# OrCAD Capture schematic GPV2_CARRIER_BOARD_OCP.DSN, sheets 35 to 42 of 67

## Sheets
35 040 M.2_L: size C
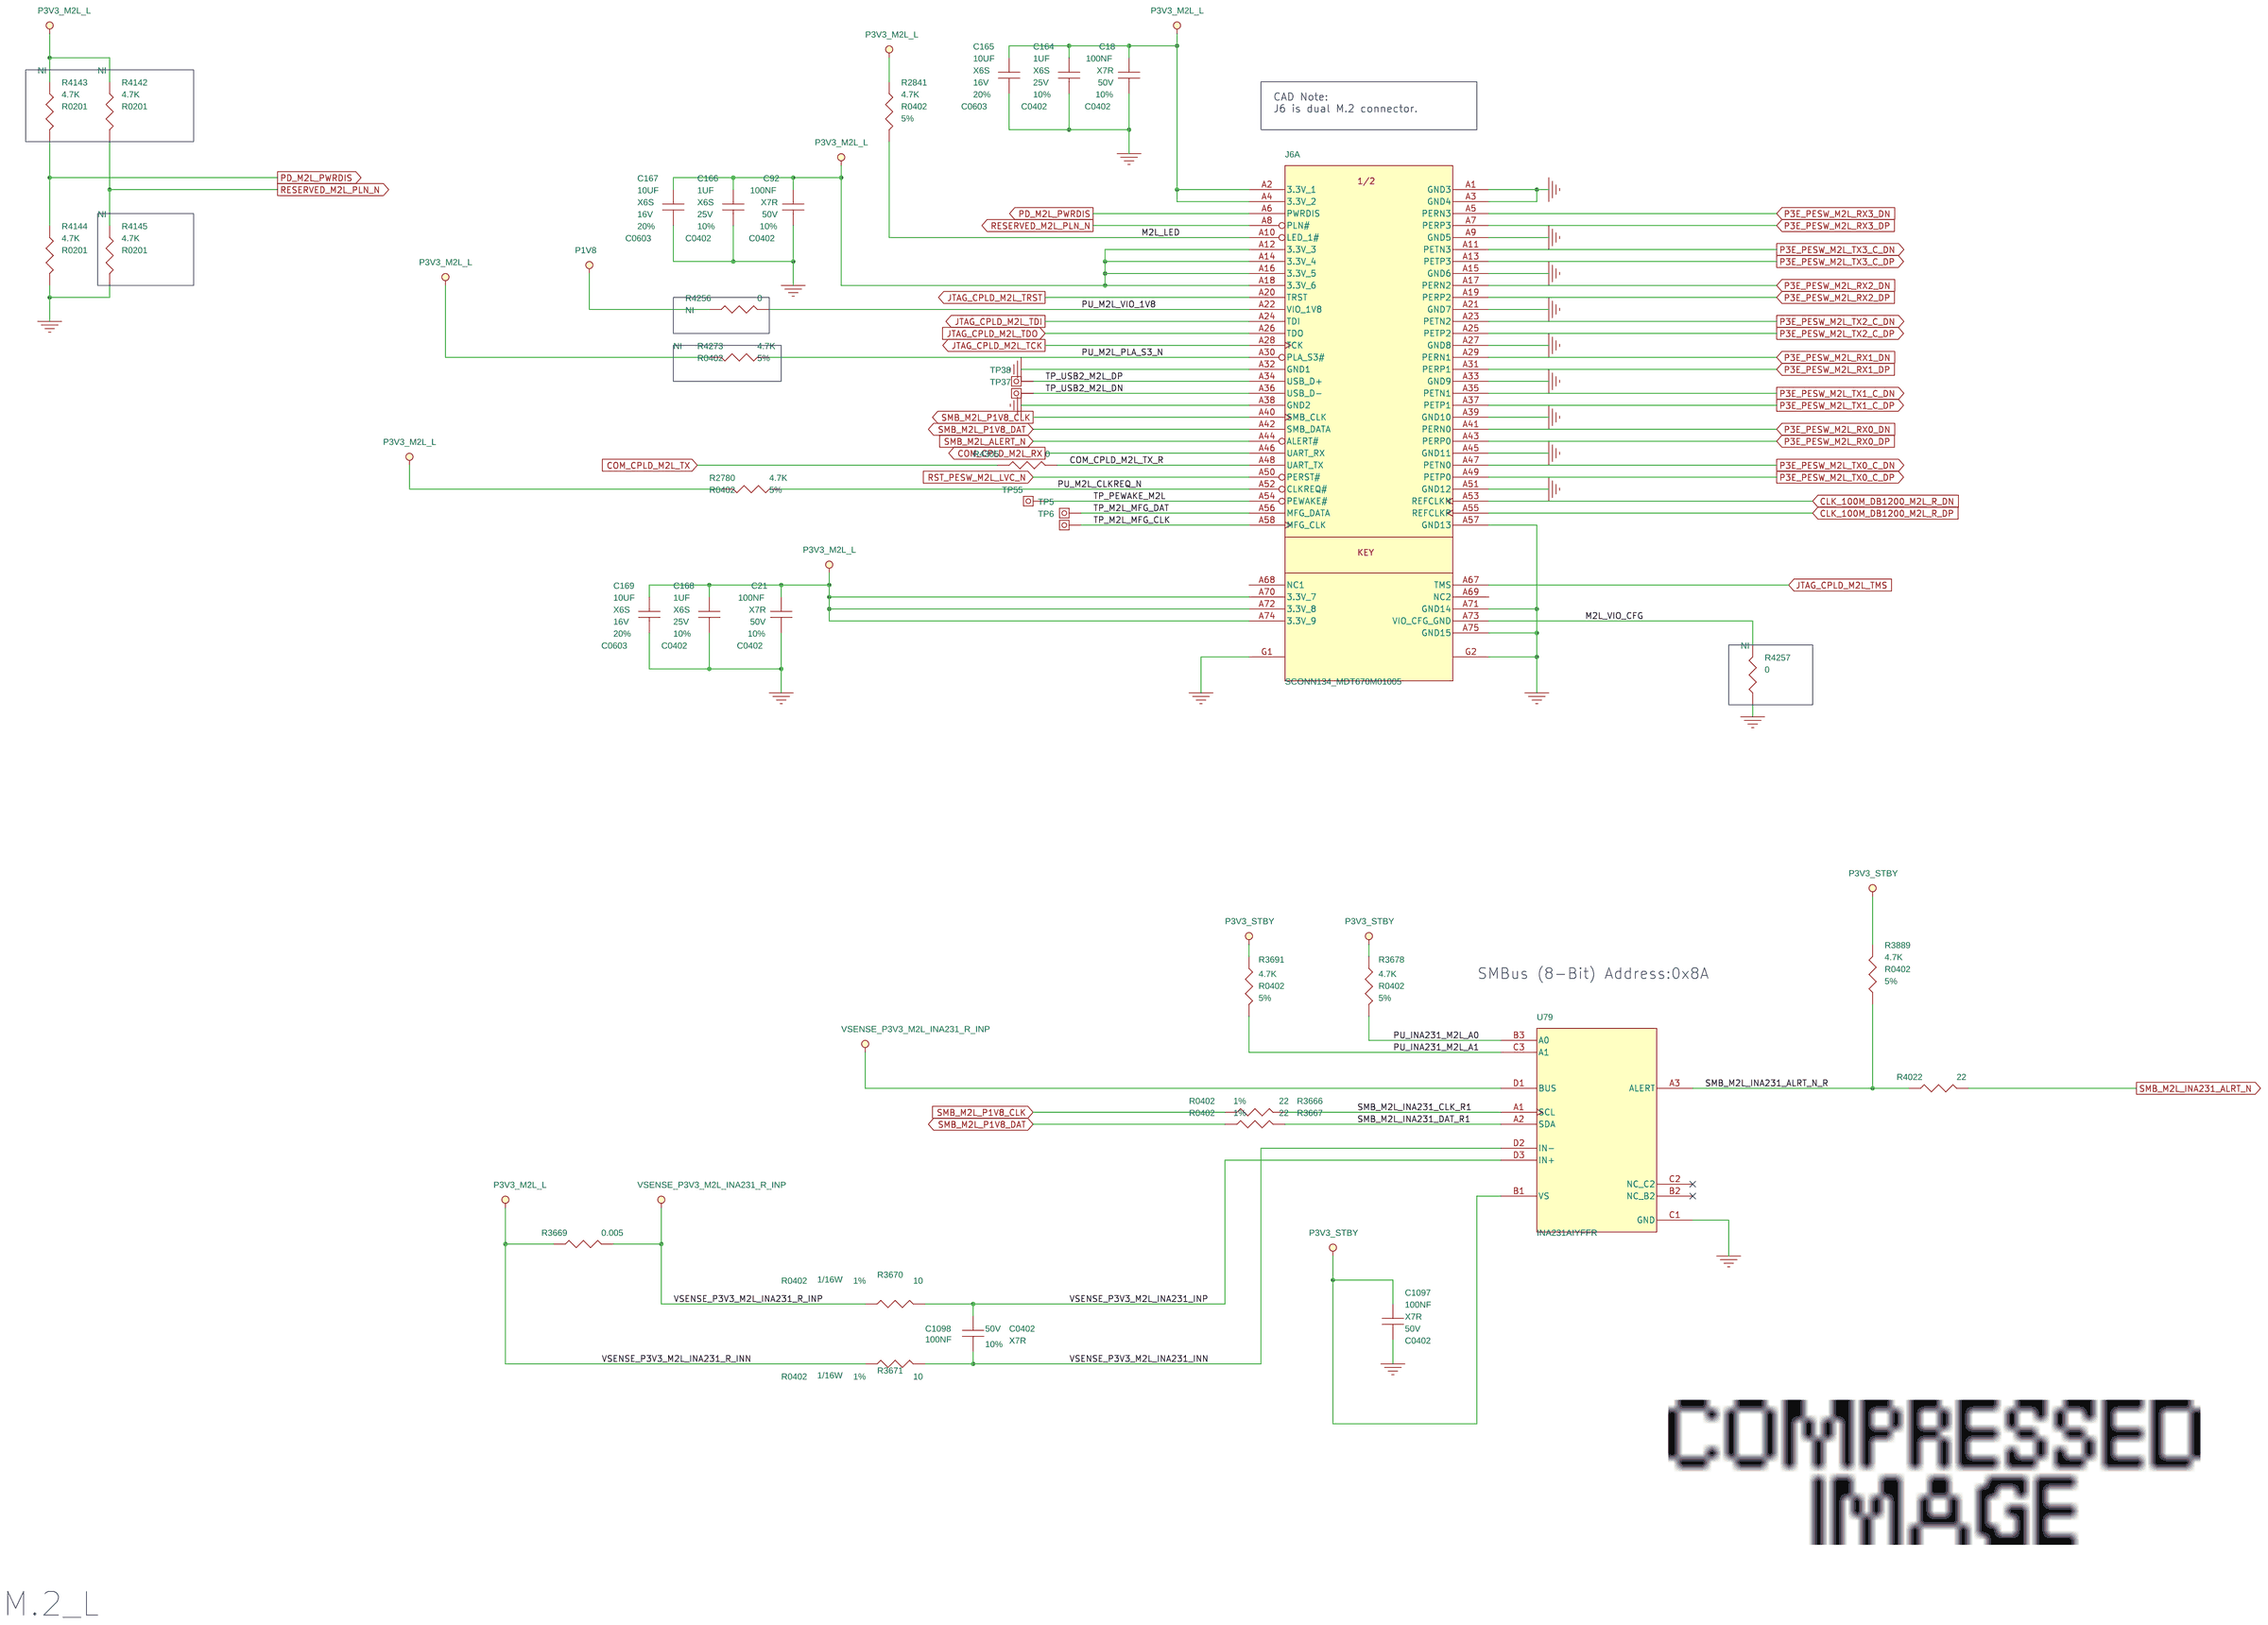
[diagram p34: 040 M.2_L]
36 042 I2C MUX 1-3: size C
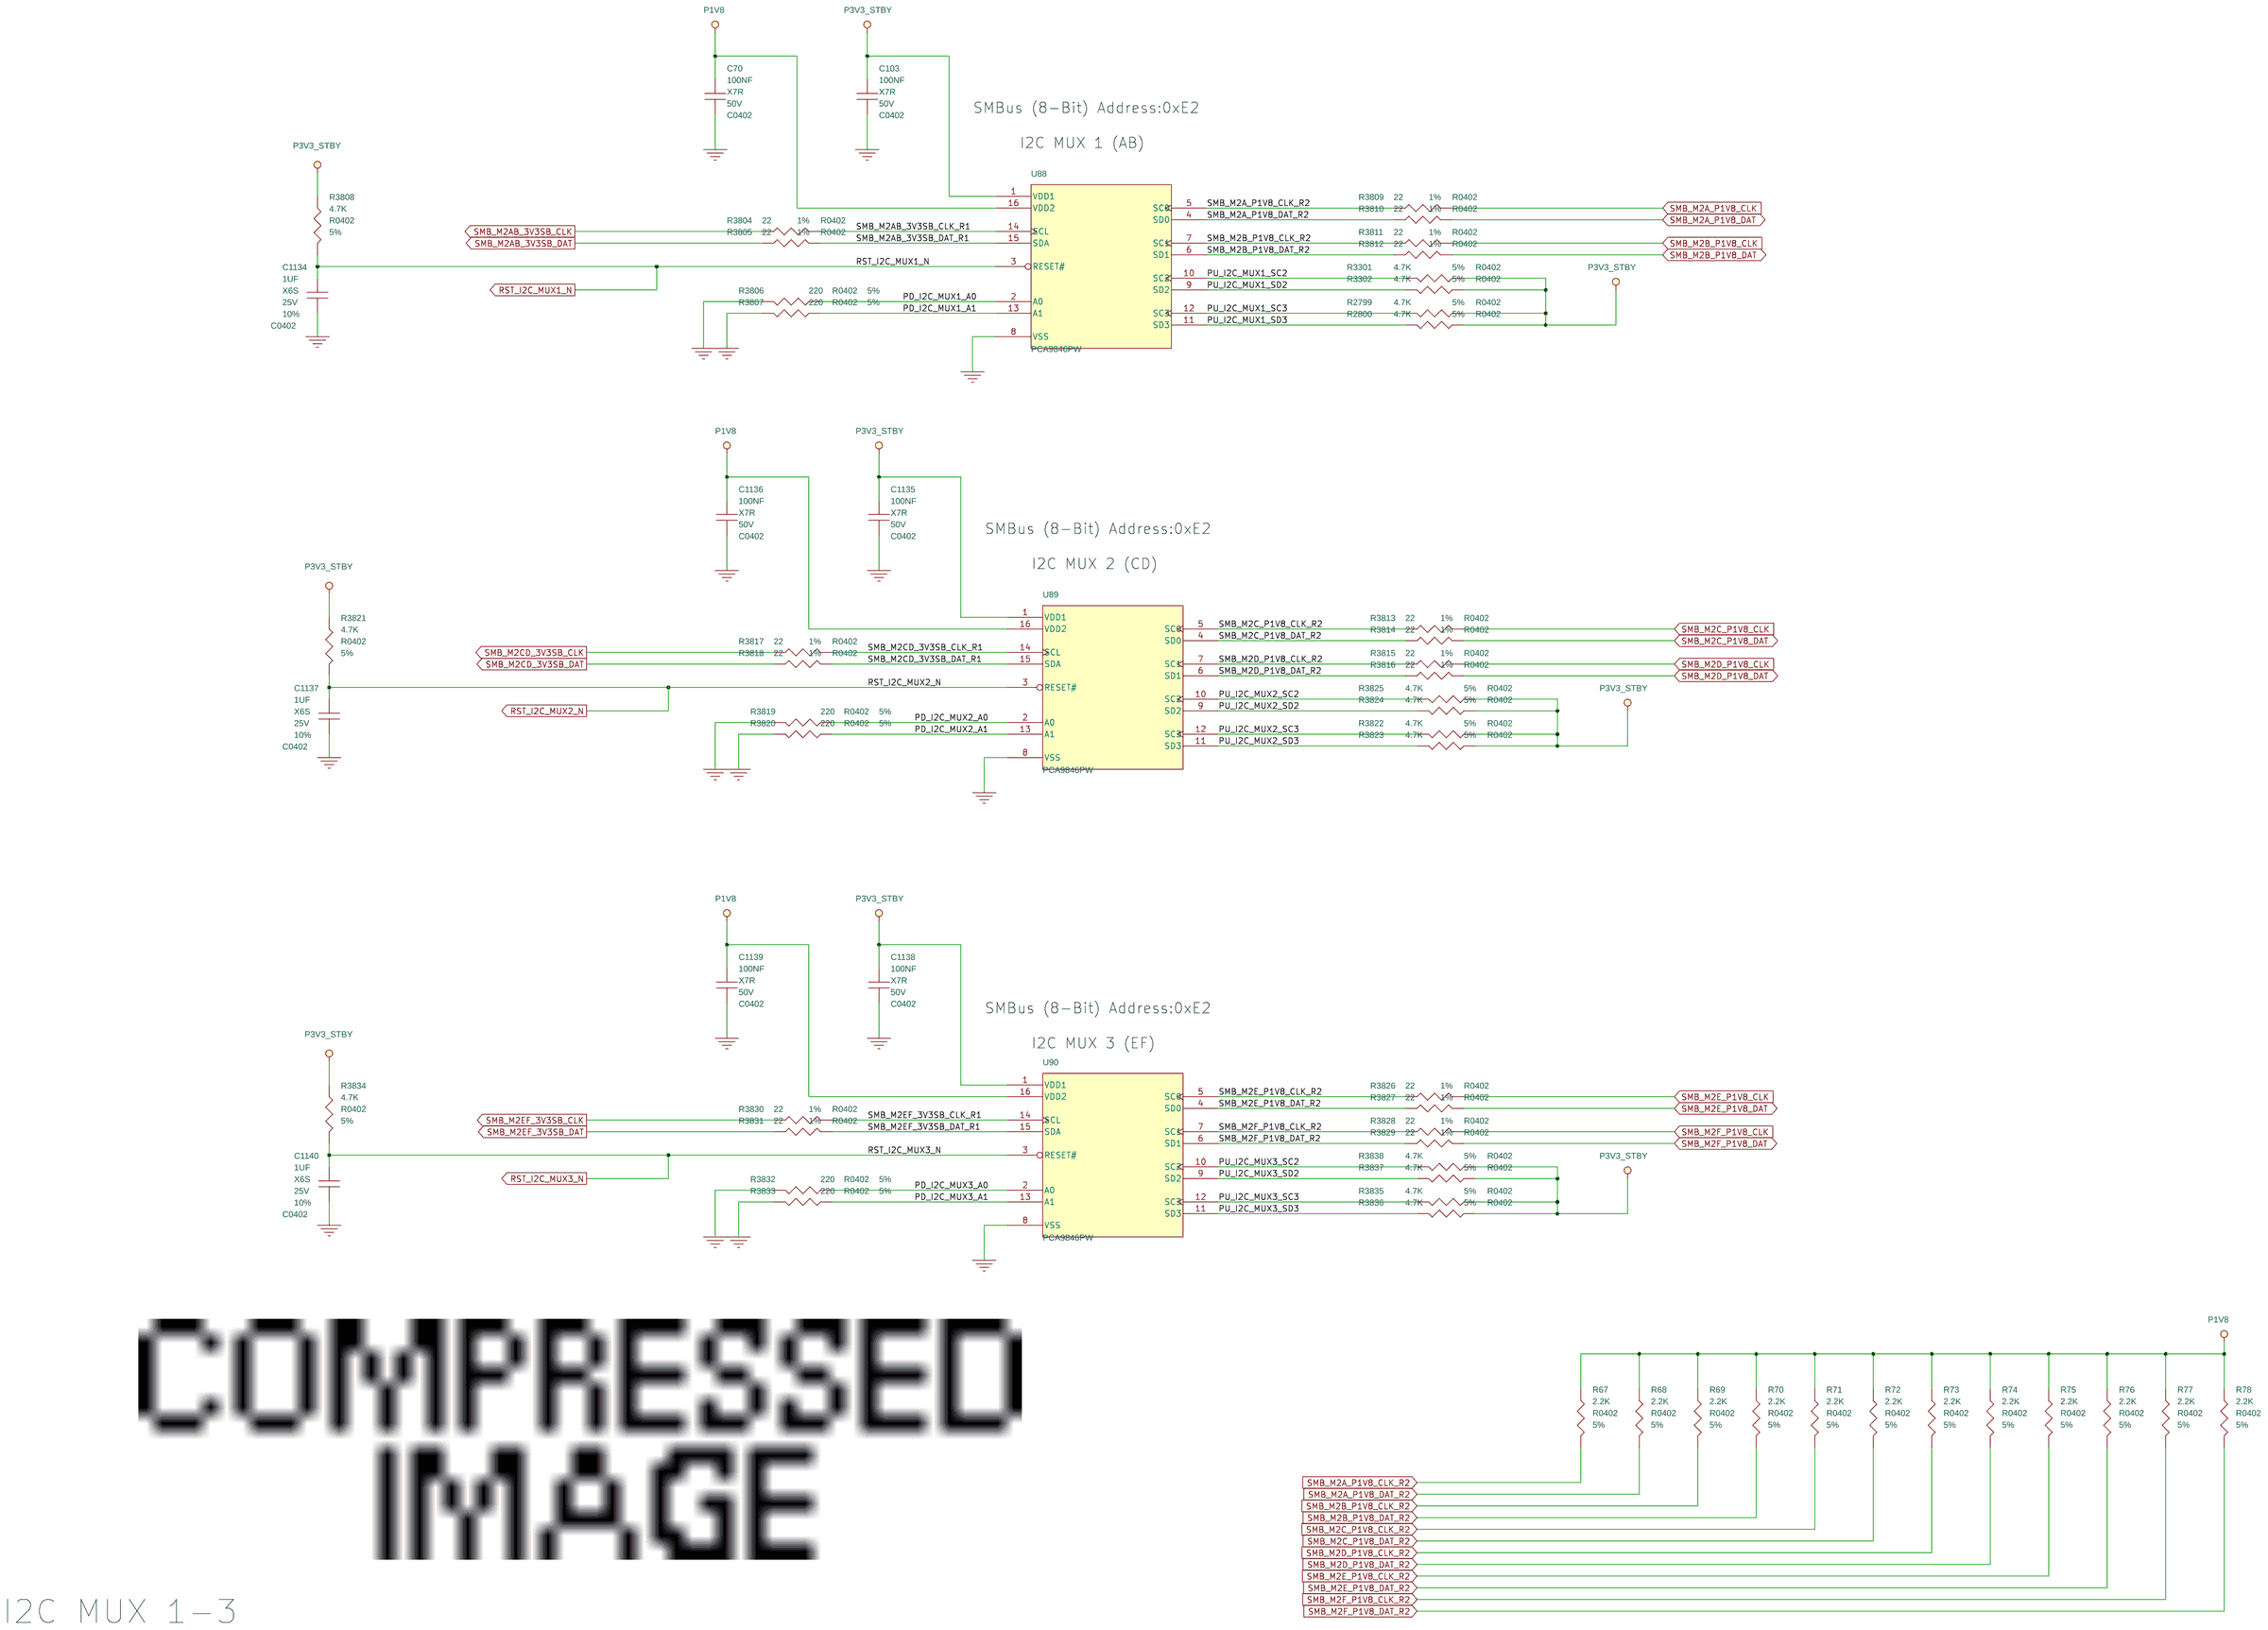
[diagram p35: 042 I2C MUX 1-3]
37 043 I2C MUX 4-6: size C
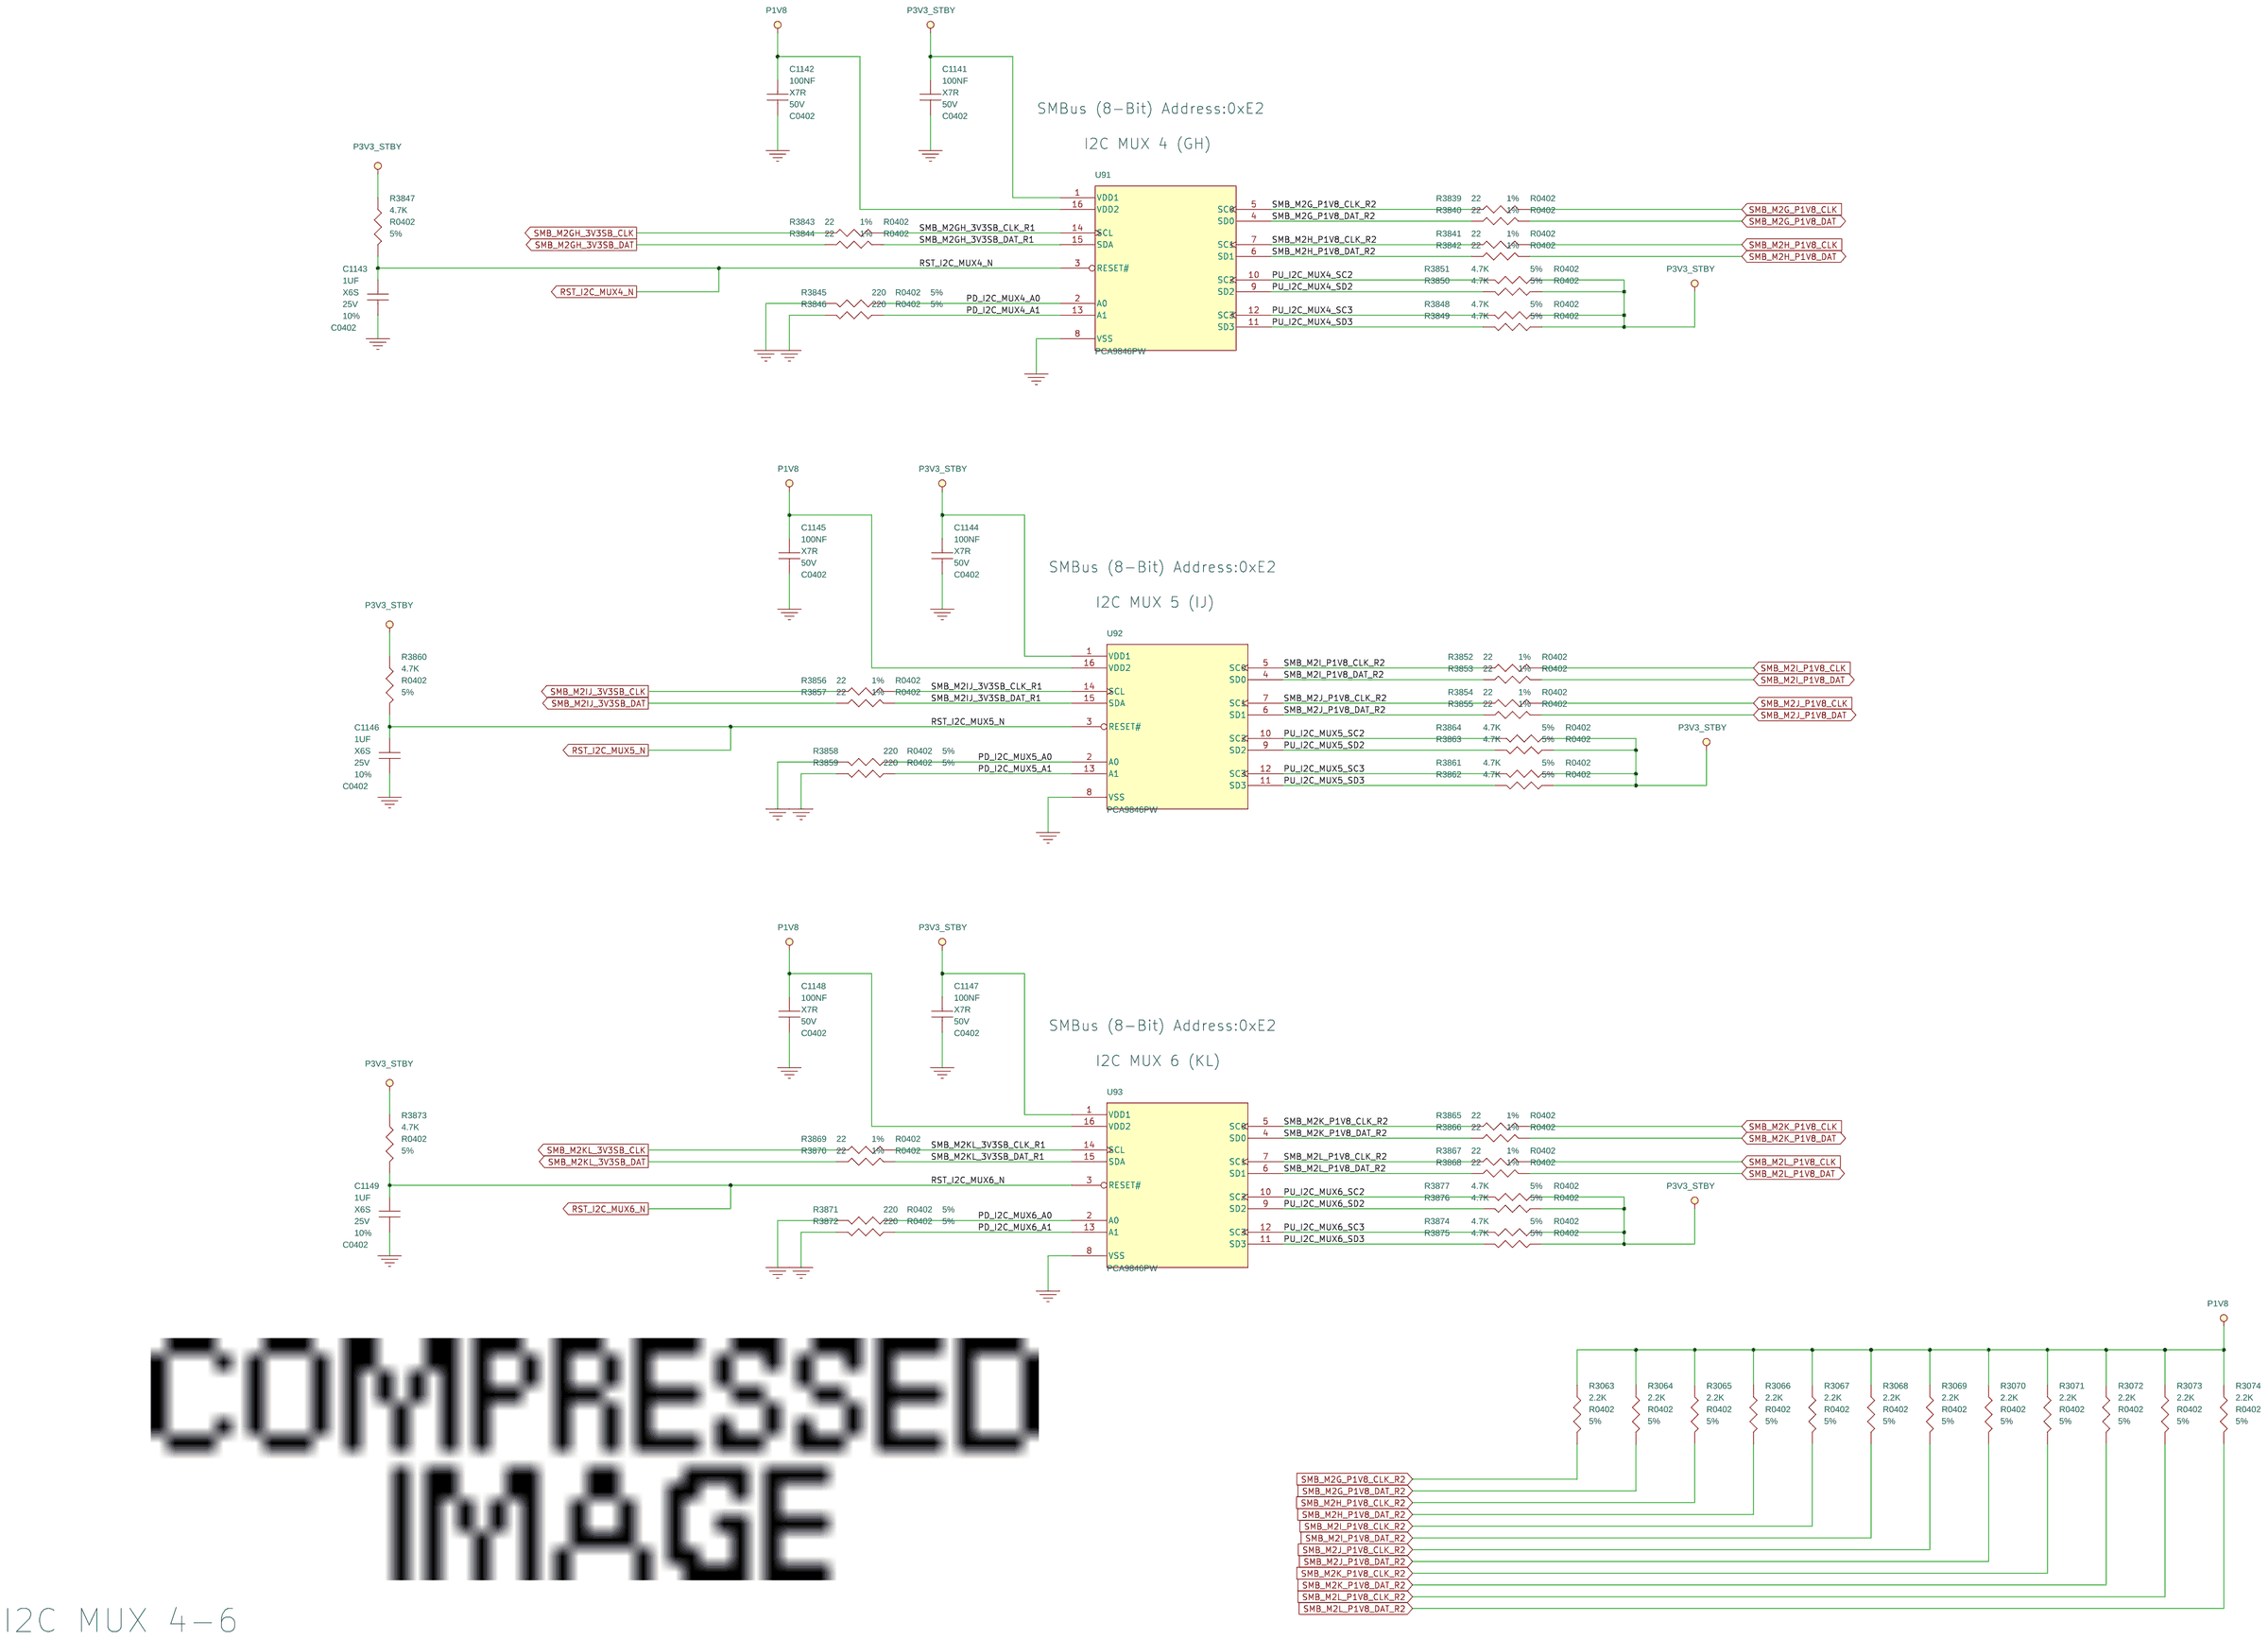
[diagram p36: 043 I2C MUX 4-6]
38 044 P3V3 M.2 POWER SWITCH 1: size C
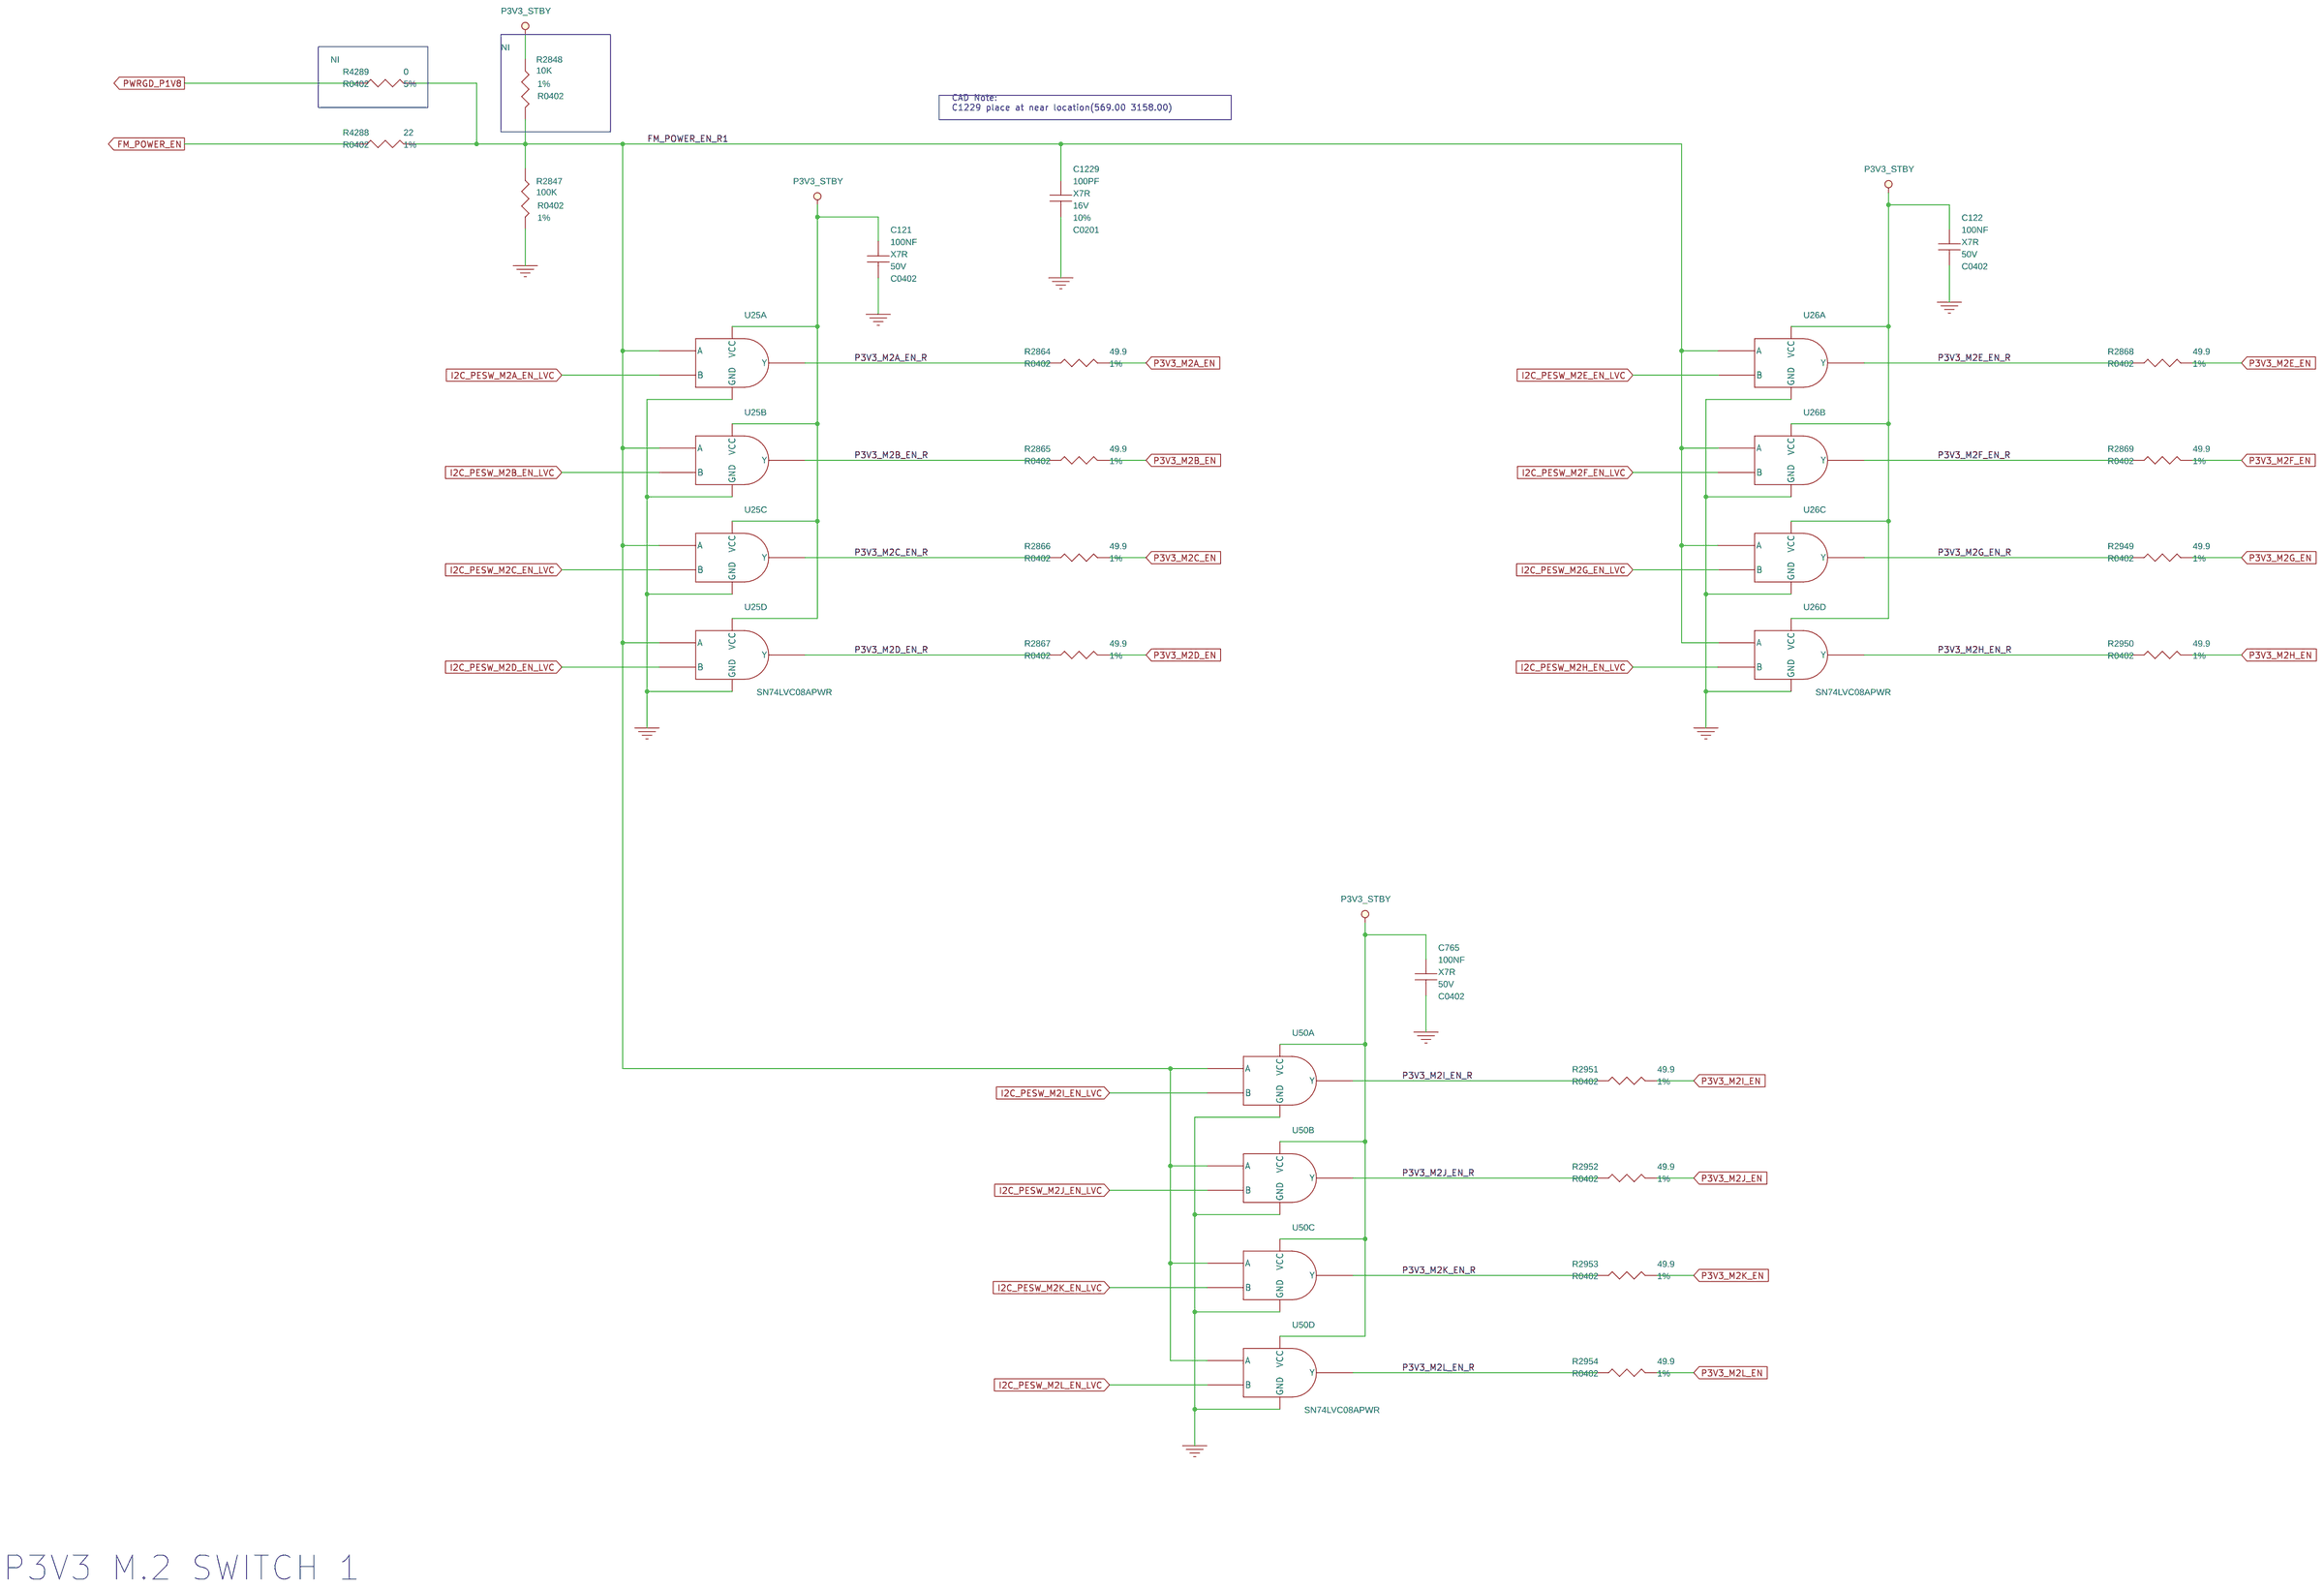
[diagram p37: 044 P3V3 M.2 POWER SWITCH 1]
39 045 P3V3 M.2 POWER SWITCH 2: size C
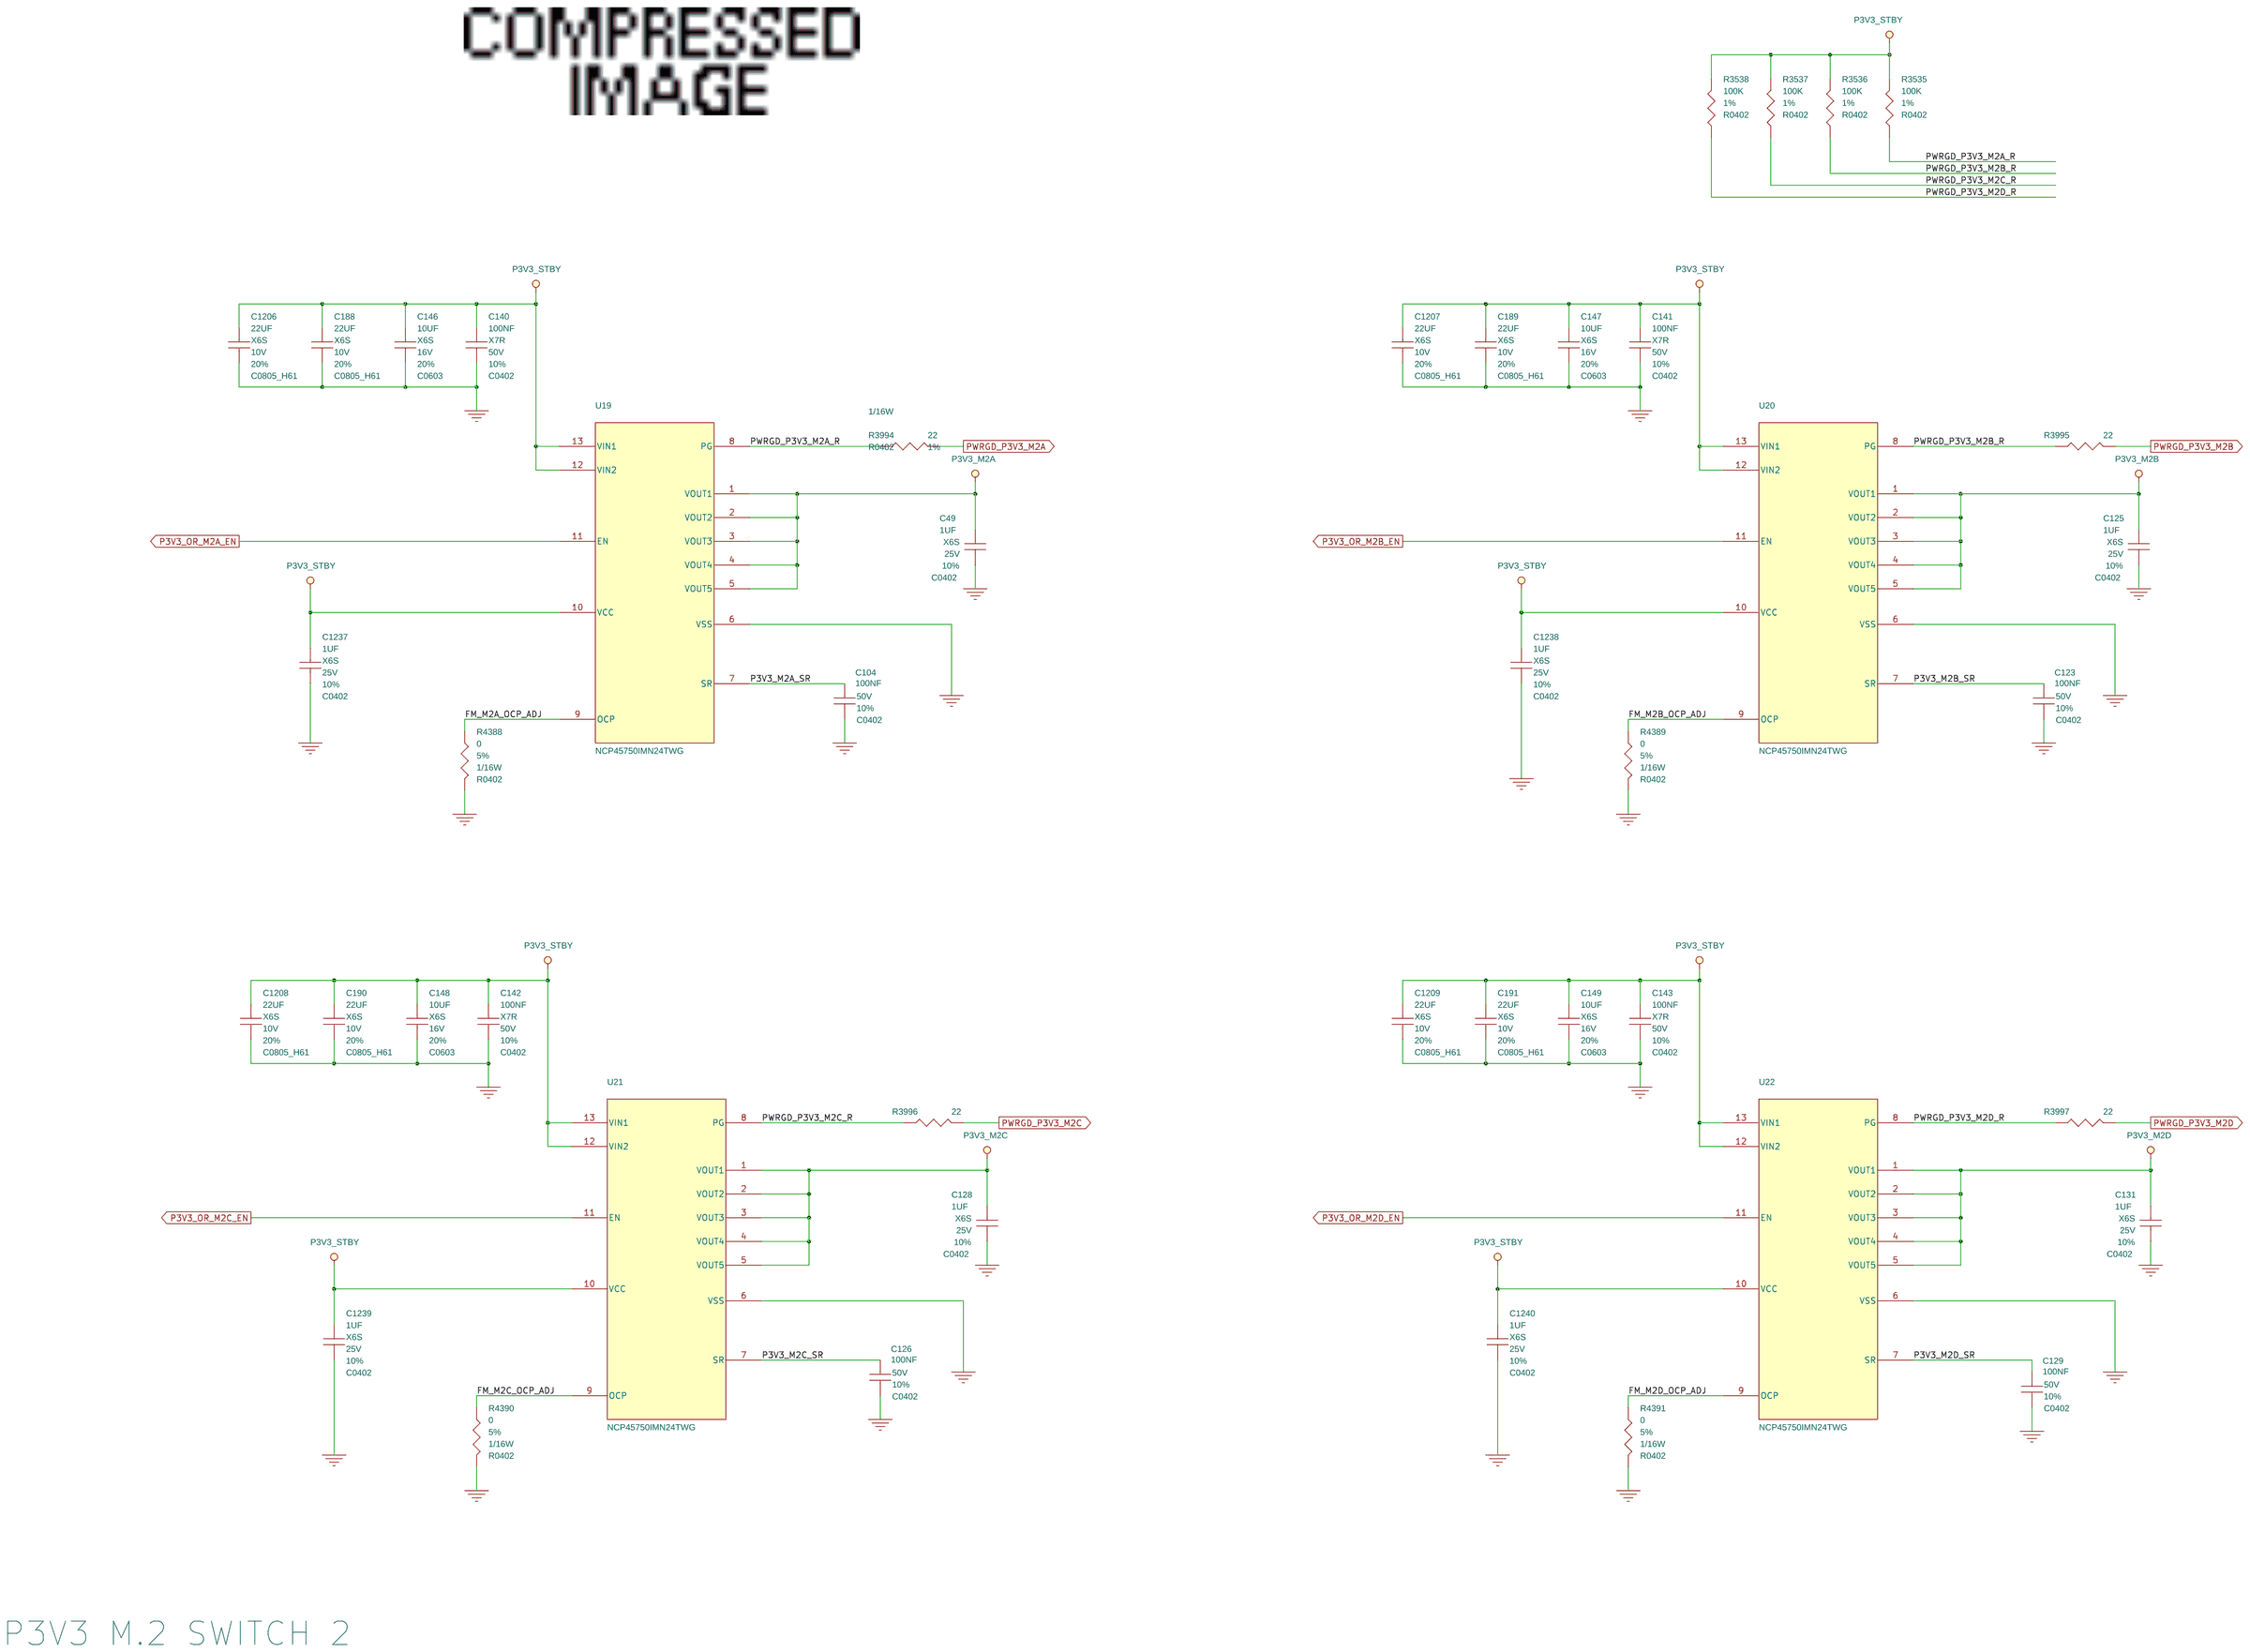
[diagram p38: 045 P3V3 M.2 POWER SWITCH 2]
40 046 P3V3 M.2 POWER SWITCH 3: size C
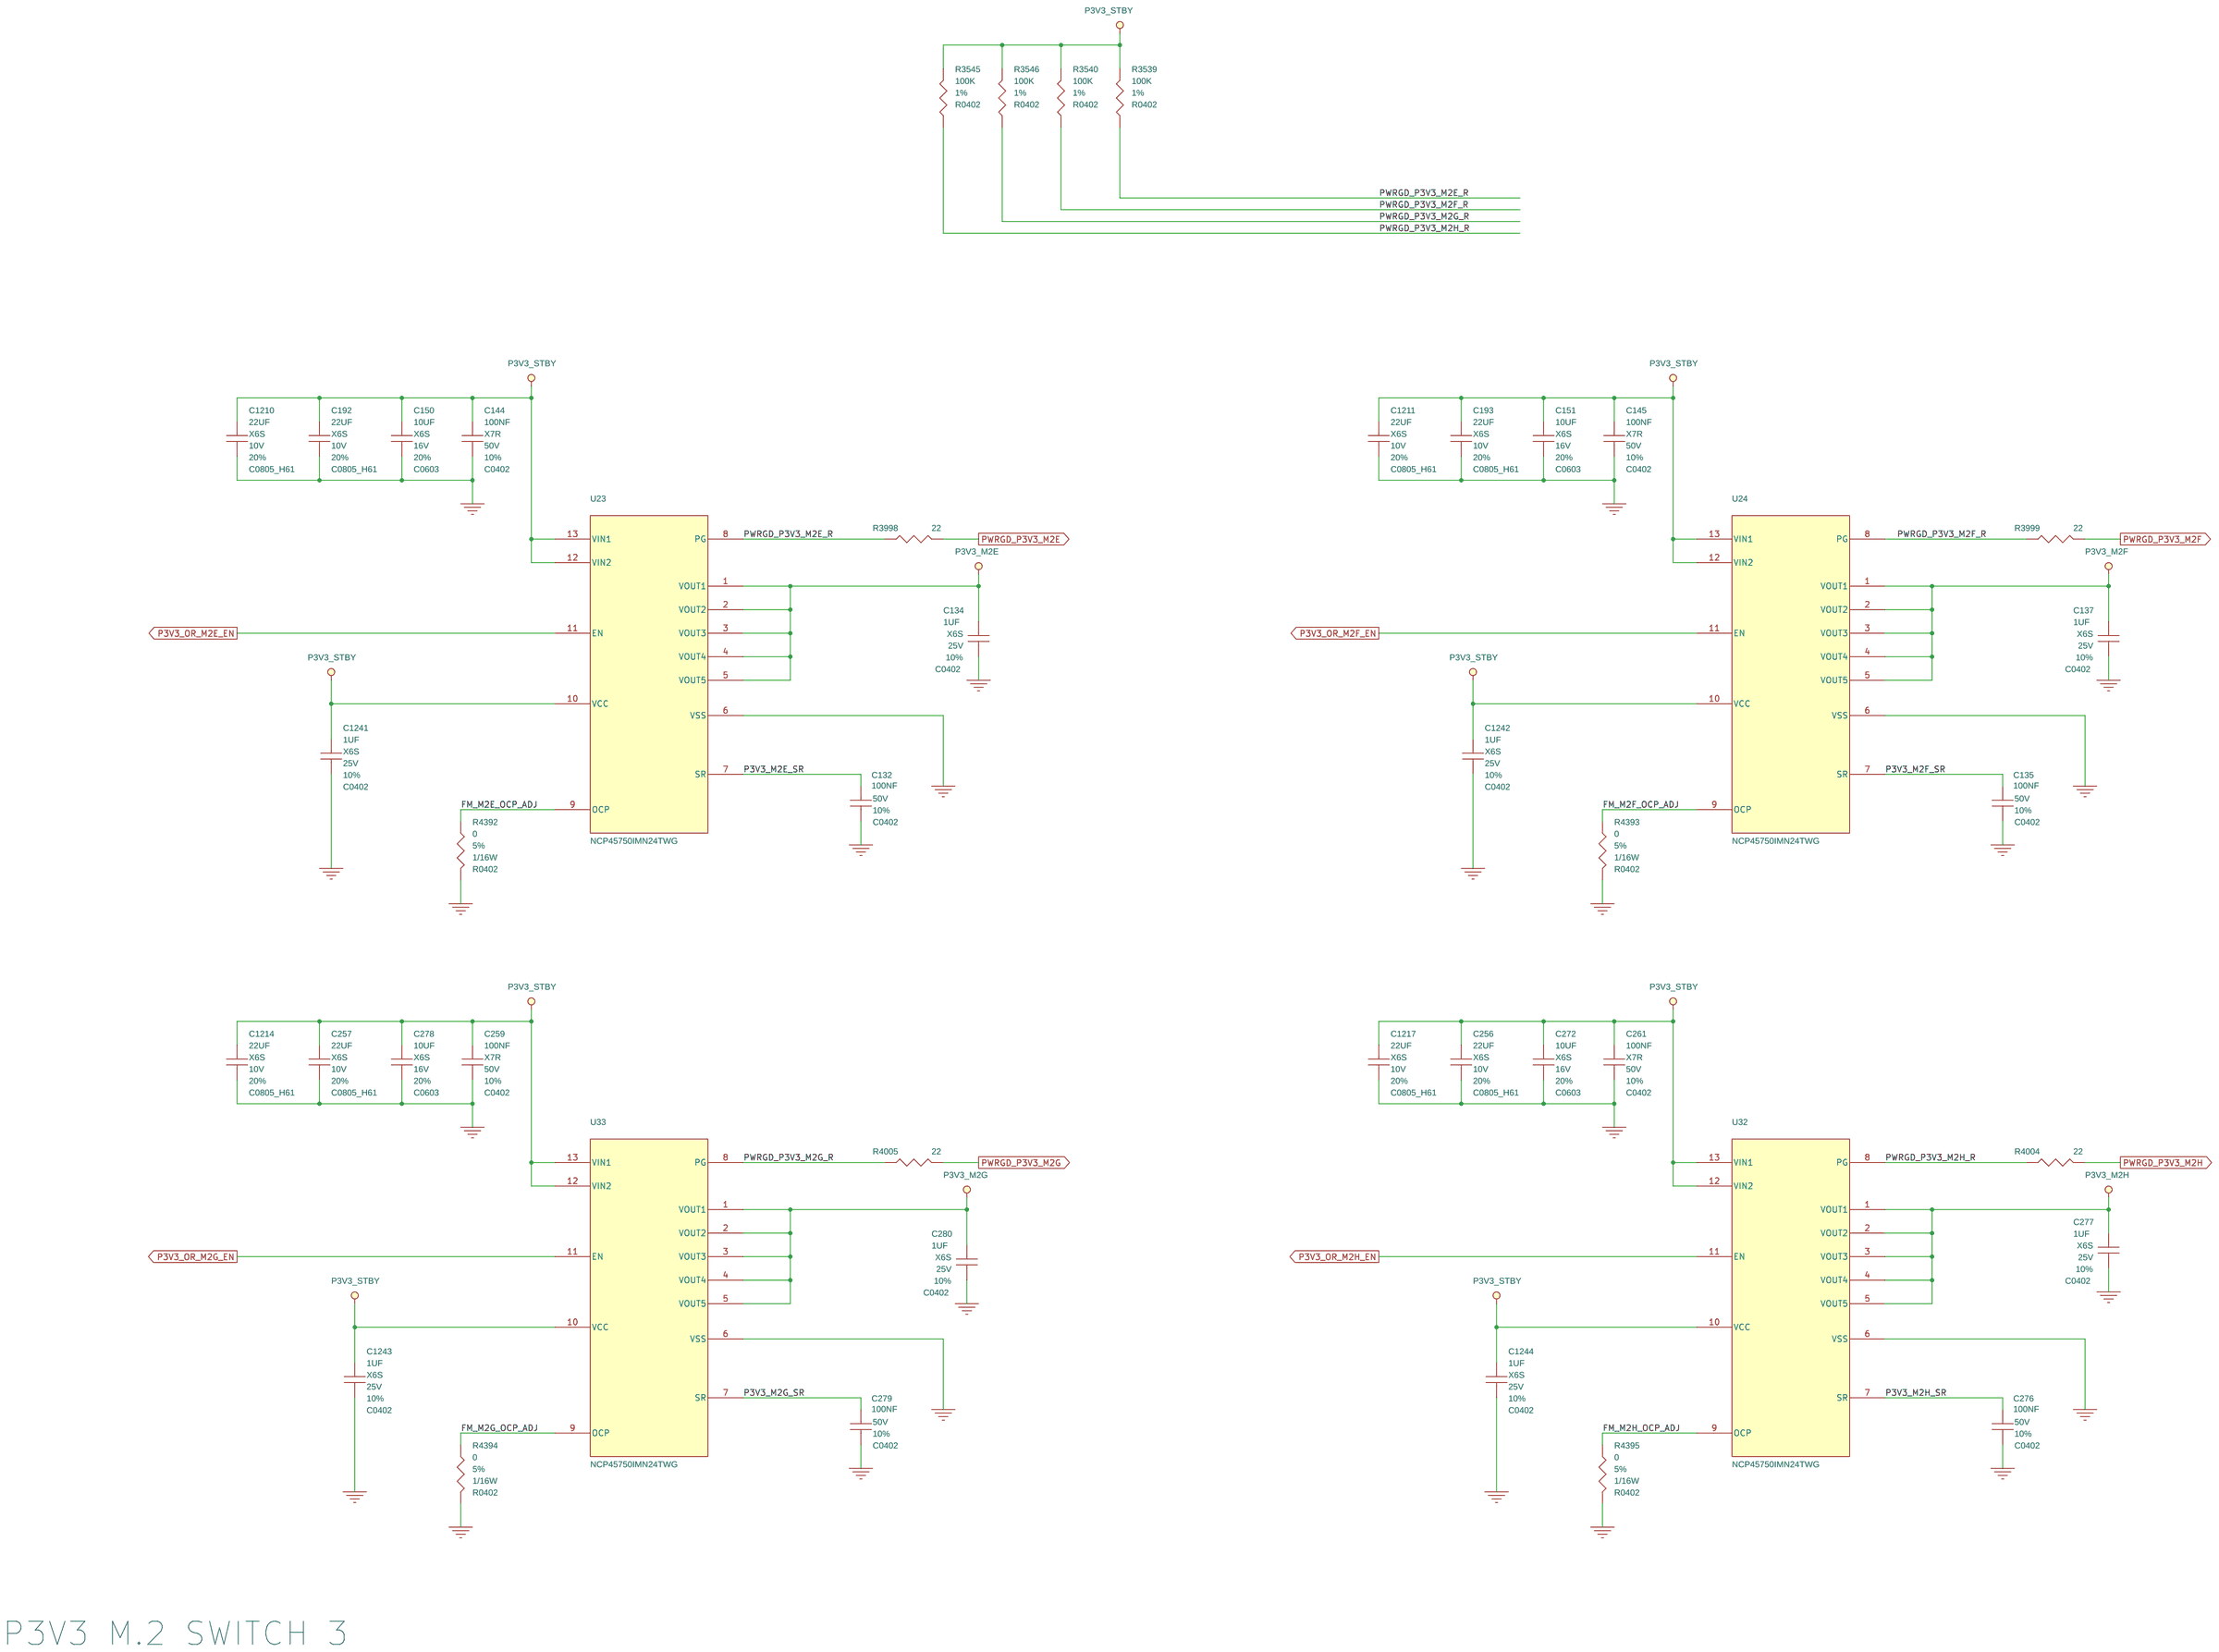
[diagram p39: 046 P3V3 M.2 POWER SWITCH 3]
41 047 P3V3 M.2 POWER SWITCH 4: size C
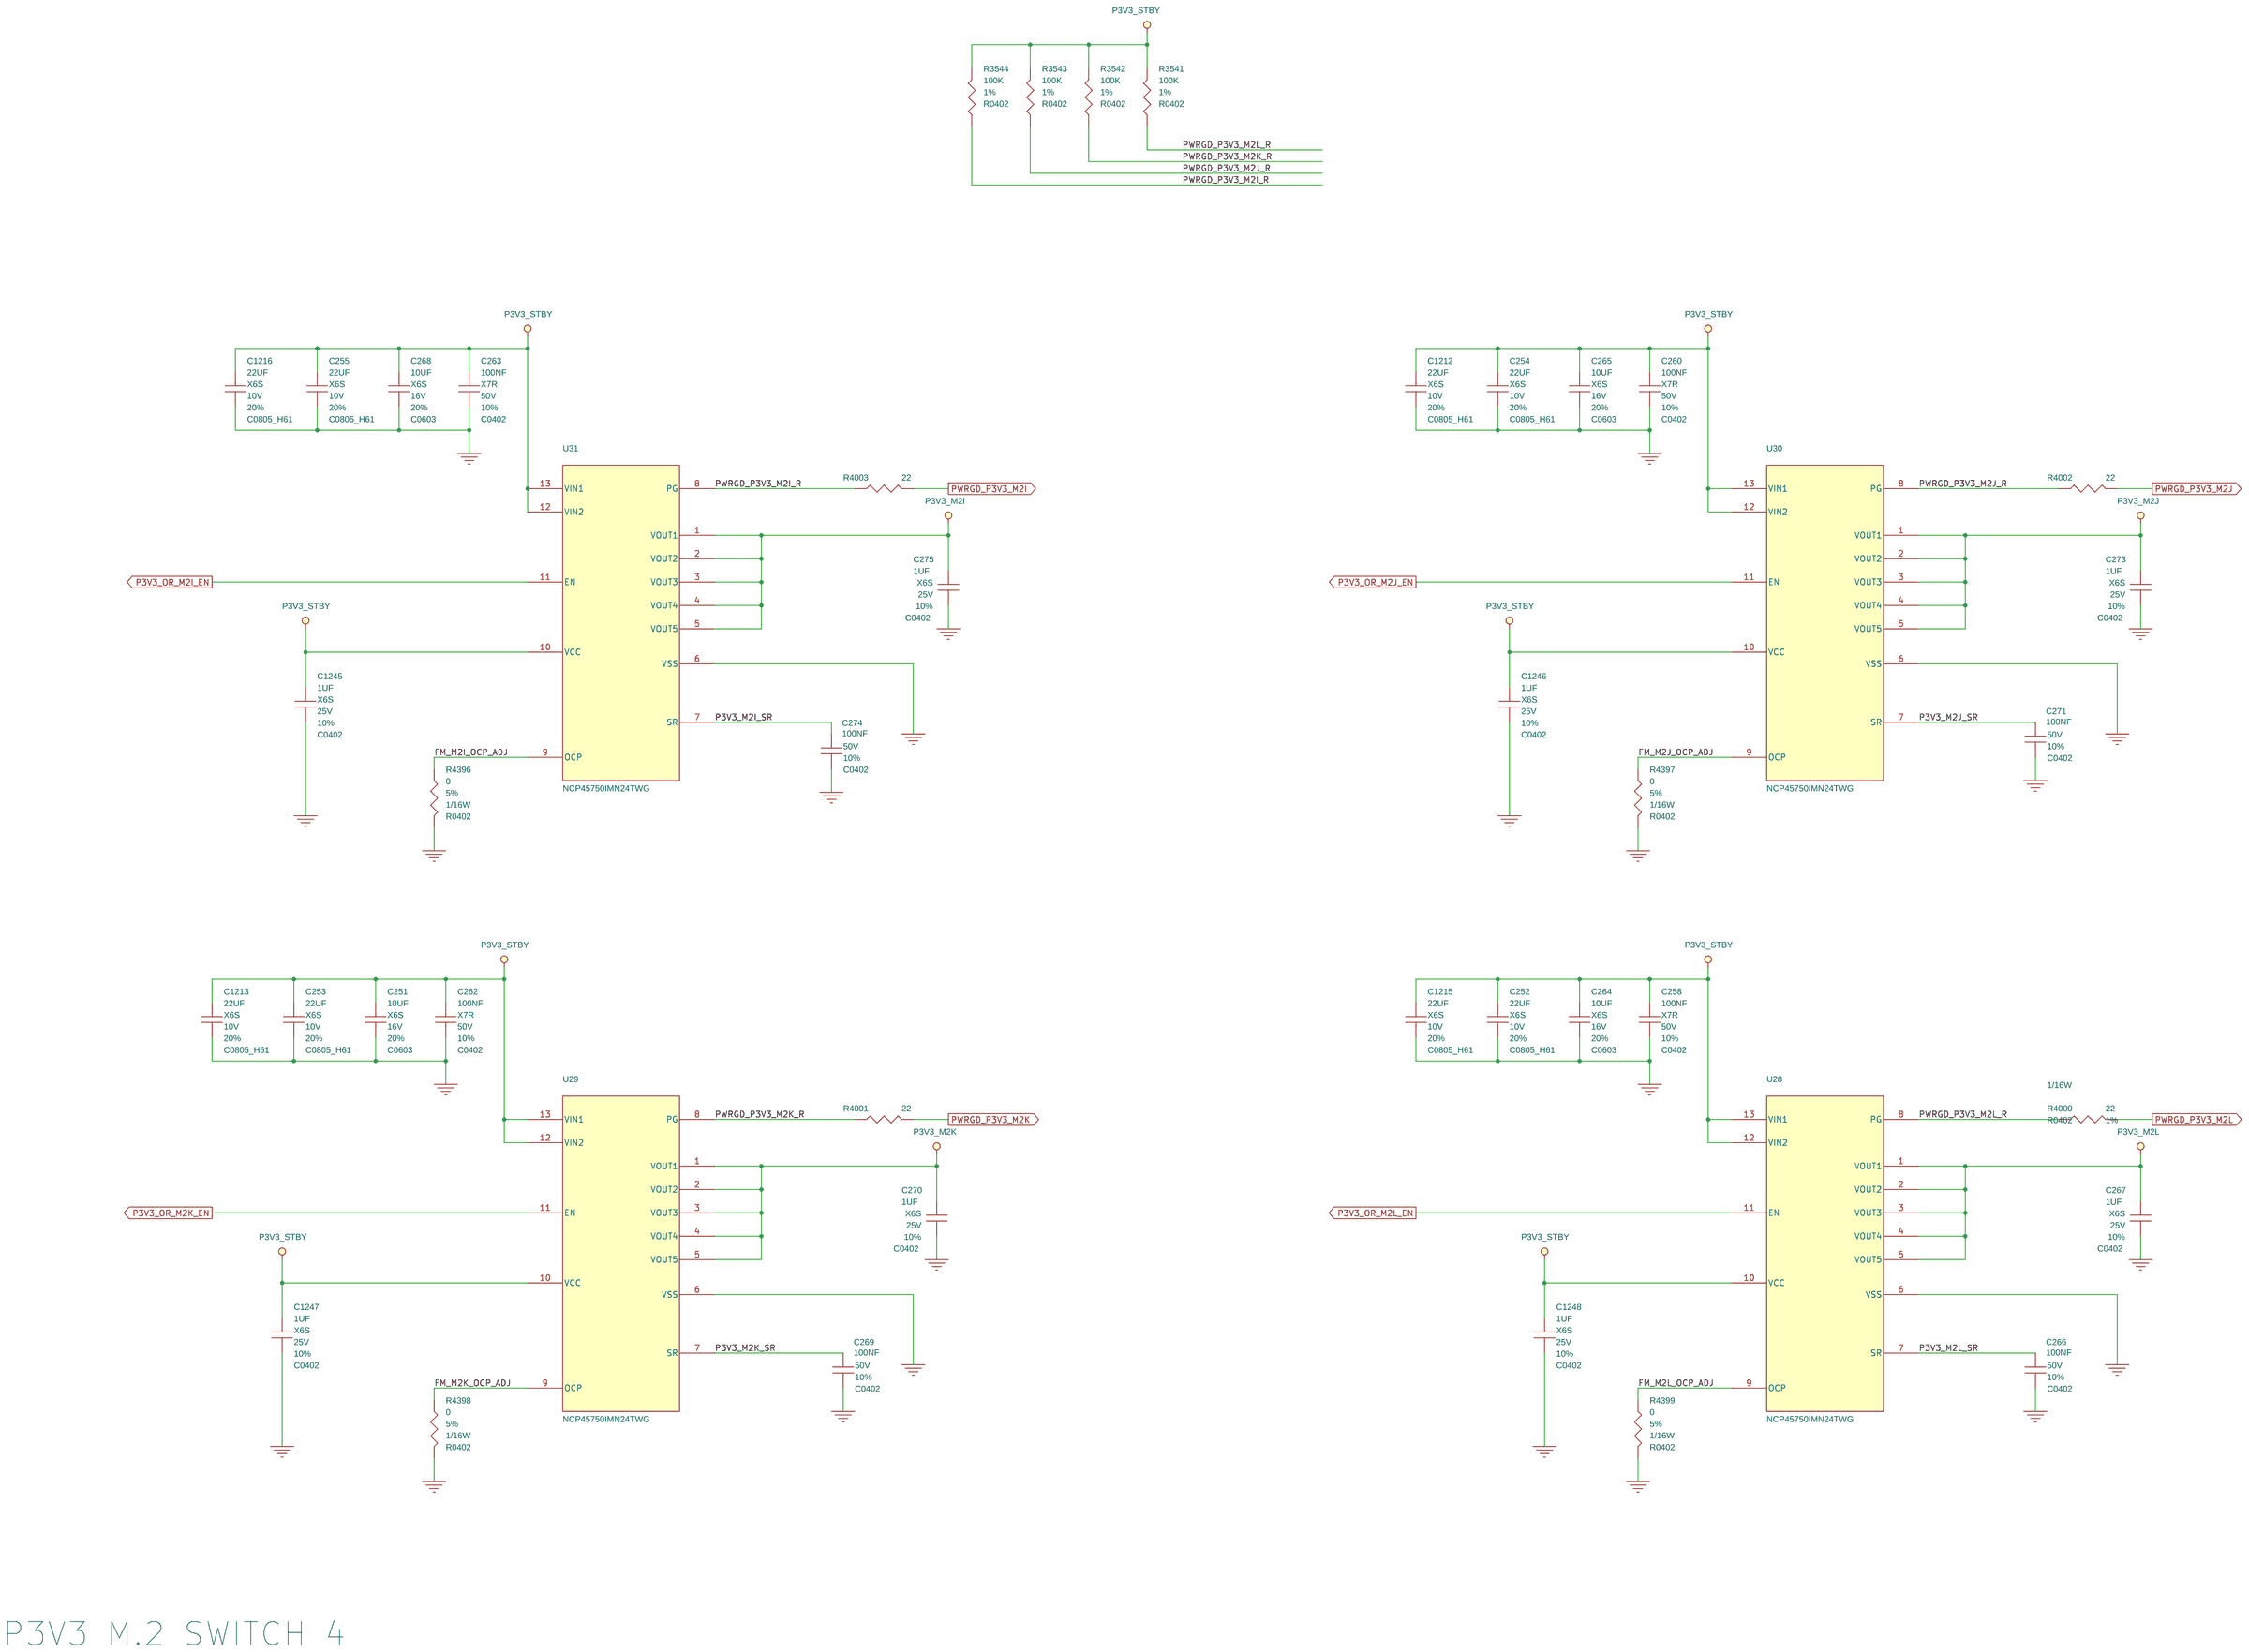
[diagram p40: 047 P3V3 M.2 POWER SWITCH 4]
42 048 LED: size C
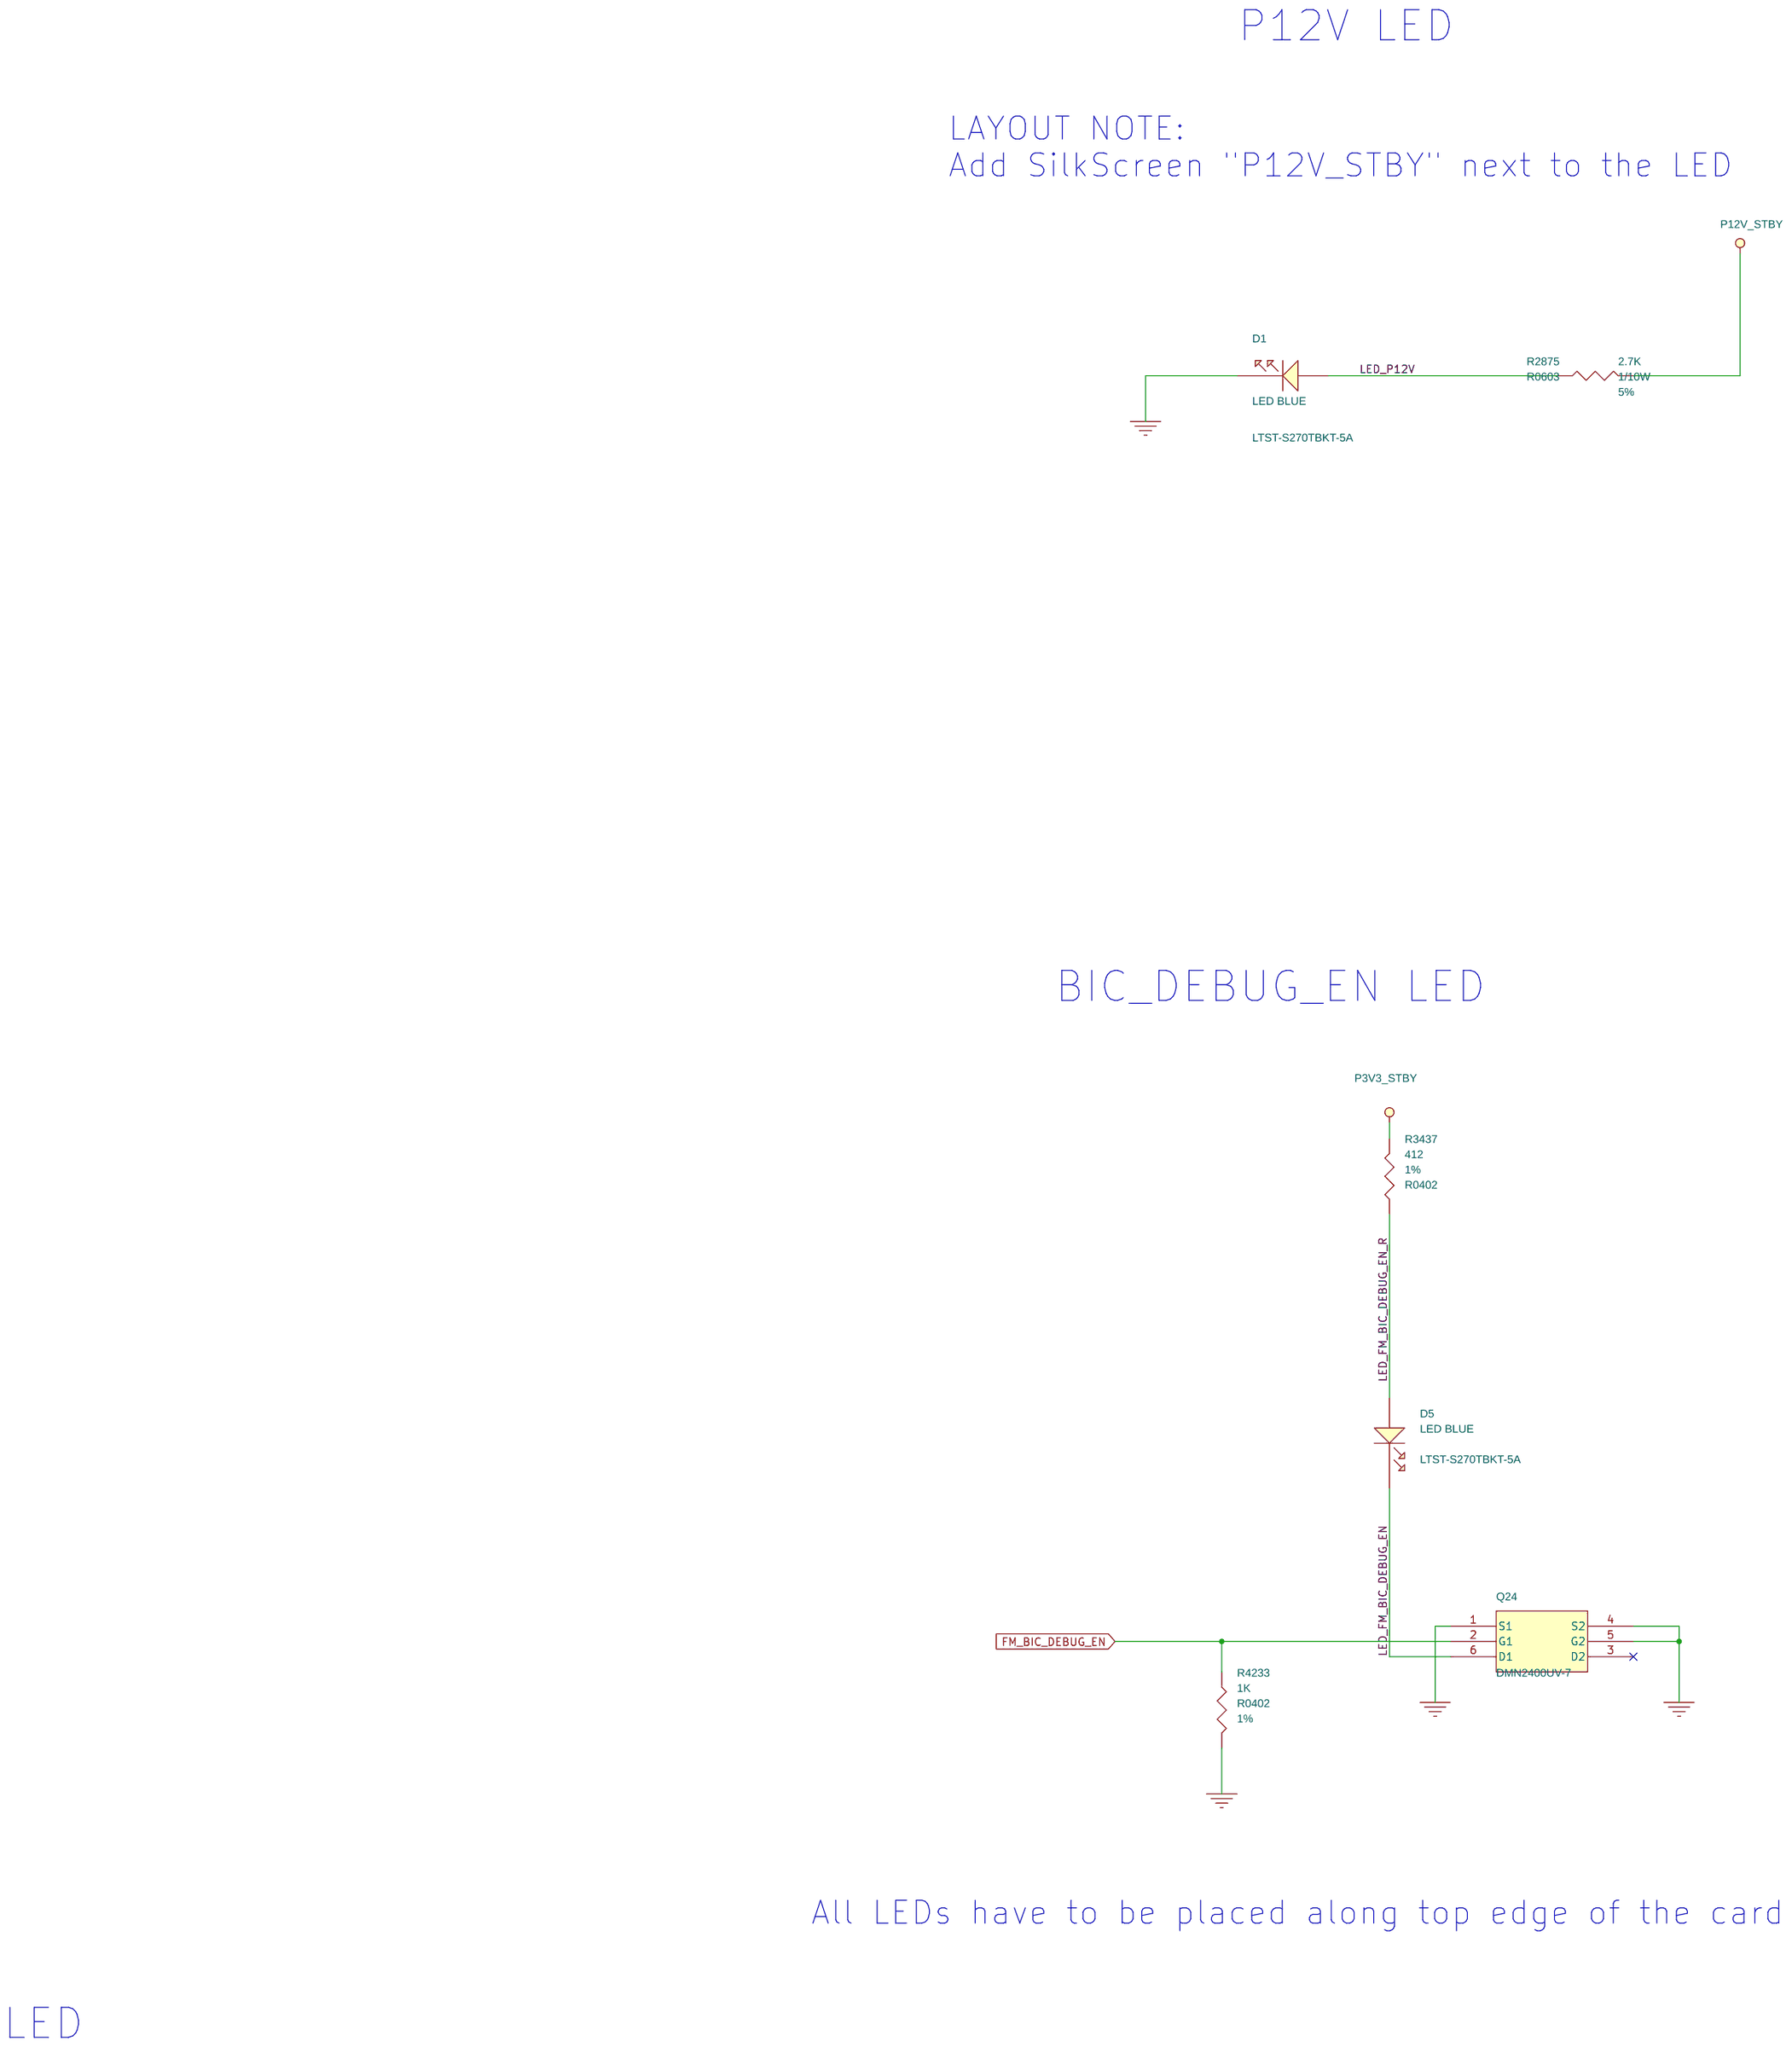
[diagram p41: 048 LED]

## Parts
sheet 039 M.2_K
J6  SCONN134_MDT670M01005  [CON_F134S2H4D4S_P0-5W7-55_LUVXA]  (sections A,B)
sheet 040 M.2_L
C18  100NF  [C0402]
C21  100NF  [C0402]
C92  100NF  [C0402]
C164  1UF  [C0402]
C165  10UF  [C0603]
C166  1UF  [C0402]
C167  10UF  [C0603]
C168  1UF  [C0402]
C169  10UF  [C0603]
C1097  100NF  [C0402]
C1098  100NF  [C0402]
R2780  4.7K  [R0402]
R2841  4.7K  [R0402]
R3666  22  [R0402]
R3667  22  [R0402]
R3669  0.005  [R1206XK]
R3670  10  [R0402]
R3671  10  [R0402]
R3678  4.7K  [R0402]
R3691  4.7K  [R0402]
R3889  4.7K  [R0402]
R4022  22  [R0402]
R4142  4.7K  [R0201]
R4143  4.7K  [R0201]
R4144  4.7K  [R0201]
R4145  4.7K  [R0201]
R4256  0  [R0402]
R4257  0  [R0402]
R4273  4.7K  [R0402]
R4305  0  [R0402]
TP5  TP  [TP26D10]
TP6  TP  [TP26D10]
TP37  TP  [TP26D10]
TP38  TP  [TP26D10]
TP55  TP  [TP26D10]
U79  INA231AIYFFR  [BGA12_0-4_1-388X1-6445]
sheet 042 I2C MUX 1-3
C70  100NF  [C0402]
C103  100NF  [C0402]
C1134  1UF  [C0402]
C1135  100NF  [C0402]
C1136  100NF  [C0402]
C1137  1UF  [C0402]
C1138  100NF  [C0402]
C1139  100NF  [C0402]
C1140  1UF  [C0402]
R67  2.2K  [R0402]
R68  2.2K  [R0402]
R69  2.2K  [R0402]
R70  2.2K  [R0402]
R71  2.2K  [R0402]
R72  2.2K  [R0402]
R73  2.2K  [R0402]
R74  2.2K  [R0402]
R75  2.2K  [R0402]
R76  2.2K  [R0402]
R77  2.2K  [R0402]
R78  2.2K  [R0402]
R2799  4.7K  [R0402]
R2800  4.7K  [R0402]
R3301  4.7K  [R0402]
R3302  4.7K  [R0402]
R3804  22  [R0402]
R3805  22  [R0402]
R3806  220  [R0402]
R3807  220  [R0402]
R3808  4.7K  [R0402]
R3809  22  [R0402]
R3810  22  [R0402]
R3811  22  [R0402]
R3812  22  [R0402]
R3813  22  [R0402]
R3814  22  [R0402]
R3815  22  [R0402]
R3816  22  [R0402]
R3817  22  [R0402]
R3818  22  [R0402]
R3819  220  [R0402]
R3820  220  [R0402]
R3821  4.7K  [R0402]
R3822  4.7K  [R0402]
R3823  4.7K  [R0402]
R3824  4.7K  [R0402]
R3825  4.7K  [R0402]
R3826  22  [R0402]
R3827  22  [R0402]
R3828  22  [R0402]
R3829  22  [R0402]
R3830  22  [R0402]
R3831  22  [R0402]
R3832  220  [R0402]
R3833  220  [R0402]
R3834  4.7K  [R0402]
R3835  4.7K  [R0402]
R3836  4.7K  [R0402]
R3837  4.7K  [R0402]
R3838  4.7K  [R0402]
U88  PCA9846PW  [TSSOP16XD]
U89  PCA9846PW  [TSSOP16XD]
U90  PCA9846PW  [TSSOP16XD]
sheet 043 I2C MUX 4-6
C1141  100NF  [C0402]
C1142  100NF  [C0402]
C1143  1UF  [C0402]
C1144  100NF  [C0402]
C1145  100NF  [C0402]
C1146  1UF  [C0402]
C1147  100NF  [C0402]
C1148  100NF  [C0402]
C1149  1UF  [C0402]
R3063  2.2K  [R0402]
R3064  2.2K  [R0402]
R3065  2.2K  [R0402]
R3066  2.2K  [R0402]
R3067  2.2K  [R0402]
R3068  2.2K  [R0402]
R3069  2.2K  [R0402]
R3070  2.2K  [R0402]
R3071  2.2K  [R0402]
R3072  2.2K  [R0402]
R3073  2.2K  [R0402]
R3074  2.2K  [R0402]
R3839  22  [R0402]
R3840  22  [R0402]
R3841  22  [R0402]
R3842  22  [R0402]
R3843  22  [R0402]
R3844  22  [R0402]
R3845  220  [R0402]
R3846  220  [R0402]
R3847  4.7K  [R0402]
R3848  4.7K  [R0402]
R3849  4.7K  [R0402]
R3850  4.7K  [R0402]
R3851  4.7K  [R0402]
R3852  22  [R0402]
R3853  22  [R0402]
R3854  22  [R0402]
R3855  22  [R0402]
R3856  22  [R0402]
R3857  22  [R0402]
R3858  220  [R0402]
R3859  220  [R0402]
R3860  4.7K  [R0402]
R3861  4.7K  [R0402]
R3862  4.7K  [R0402]
R3863  4.7K  [R0402]
R3864  4.7K  [R0402]
R3865  22  [R0402]
R3866  22  [R0402]
R3867  22  [R0402]
R3868  22  [R0402]
R3869  22  [R0402]
R3870  22  [R0402]
R3871  220  [R0402]
R3872  220  [R0402]
R3873  4.7K  [R0402]
R3874  4.7K  [R0402]
R3875  4.7K  [R0402]
R3876  4.7K  [R0402]
R3877  4.7K  [R0402]
U91  PCA9846PW  [TSSOP16XD]
U92  PCA9846PW  [TSSOP16XD]
U93  PCA9846PW  [TSSOP16XD]
sheet 044 P3V3 M.2 POWER SWITCH 1
C121  100NF  [C0402]
C122  100NF  [C0402]
C765  100NF  [C0402]
C1229  100PF  [C0201]
R2847  100K  [R0402]
R2848  10K  [R0402]
R2864  49.9  [R0402]
R2865  49.9  [R0402]
R2866  49.9  [R0402]
R2867  49.9  [R0402]
R2868  49.9  [R0402]
R2869  49.9  [R0402]
R2949  49.9  [R0402]
R2950  49.9  [R0402]
R2951  49.9  [R0402]
R2952  49.9  [R0402]
R2953  49.9  [R0402]
R2954  49.9  [R0402]
R4288  22  [R0402]
R4289  0  [R0402]
U25  SN74LVC08APWR  [TSSOP14]  (sections A,B,C,D)
U26  SN74LVC08APWR  [TSSOP14]  (sections A,B,C,D)
U50  SN74LVC08APWR  [TSSOP14]  (sections A,B,C,D)
sheet 045 P3V3 M.2 POWER SWITCH 2
C49  1UF  [C0402]
C104  100NF  [C0402]
C123  100NF  [C0402]
C125  1UF  [C0402]
C126  100NF  [C0402]
C128  1UF  [C0402]
C129  100NF  [C0402]
C131  1UF  [C0402]
C140  100NF  [C0402]
C141  100NF  [C0402]
C142  100NF  [C0402]
C143  100NF  [C0402]
C146  10UF  [C0603]
C147  10UF  [C0603]
C148  10UF  [C0603]
C149  10UF  [C0603]
C188  22UF  [C0805_H61]
C189  22UF  [C0805_H61]
C190  22UF  [C0805_H61]
C191  22UF  [C0805_H61]
C1206  22UF  [C0805_H61]
C1207  22UF  [C0805_H61]
C1208  22UF  [C0805_H61]
C1209  22UF  [C0805_H61]
C1237  1UF  [C0402]
C1238  1UF  [C0402]
C1239  1UF  [C0402]
C1240  1UF  [C0402]
R3535  100K  [R0402]
R3536  100K  [R0402]
R3537  100K  [R0402]
R3538  100K  [R0402]
R3994  22  [R0402]
R3995  22  [R0402]
R3996  22  [R0402]
R3997  22  [R0402]
R4388  0  [R0402]
R4389  0  [R0402]
R4390  0  [R0402]
R4391  0  [R0402]
U19  NCP45750IMN24TWG  [DFN12_TH_0-5_3X3XA]
U20  NCP45750IMN24TWG  [DFN12_TH_0-5_3X3XA]
U21  NCP45750IMN24TWG  [DFN12_TH_0-5_3X3XA]
U22  NCP45750IMN24TWG  [DFN12_TH_0-5_3X3XA]
sheet 046 P3V3 M.2 POWER SWITCH 3
C132  100NF  [C0402]
C134  1UF  [C0402]
C135  100NF  [C0402]
C137  1UF  [C0402]
C144  100NF  [C0402]
C145  100NF  [C0402]
C150  10UF  [C0603]
C151  10UF  [C0603]
C192  22UF  [C0805_H61]
C193  22UF  [C0805_H61]
C256  22UF  [C0805_H61]
C257  22UF  [C0805_H61]
C259  100NF  [C0402]
C261  100NF  [C0402]
C272  10UF  [C0603]
C276  100NF  [C0402]
C277  1UF  [C0402]
C278  10UF  [C0603]
C279  100NF  [C0402]
C280  1UF  [C0402]
C1210  22UF  [C0805_H61]
C1211  22UF  [C0805_H61]
C1214  22UF  [C0805_H61]
C1217  22UF  [C0805_H61]
C1241  1UF  [C0402]
C1242  1UF  [C0402]
C1243  1UF  [C0402]
C1244  1UF  [C0402]
R3539  100K  [R0402]
R3540  100K  [R0402]
R3545  100K  [R0402]
R3546  100K  [R0402]
R3998  22  [R0402]
R3999  22  [R0402]
R4004  22  [R0402]
R4005  22  [R0402]
R4392  0  [R0402]
R4393  0  [R0402]
R4394  0  [R0402]
R4395  0  [R0402]
U23  NCP45750IMN24TWG  [DFN12_TH_0-5_3X3XA]
U24  NCP45750IMN24TWG  [DFN12_TH_0-5_3X3XA]
U32  NCP45750IMN24TWG  [DFN12_TH_0-5_3X3XA]
U33  NCP45750IMN24TWG  [DFN12_TH_0-5_3X3XA]
sheet 047 P3V3 M.2 POWER SWITCH 4
C251  10UF  [C0603]
C252  22UF  [C0805_H61]
C253  22UF  [C0805_H61]
C254  22UF  [C0805_H61]
C255  22UF  [C0805_H61]
C258  100NF  [C0402]
C260  100NF  [C0402]
C262  100NF  [C0402]
C263  100NF  [C0402]
C264  10UF  [C0603]
C265  10UF  [C0603]
C266  100NF  [C0402]
C267  1UF  [C0402]
C268  10UF  [C0603]
C269  100NF  [C0402]
C270  1UF  [C0402]
C271  100NF  [C0402]
C273  1UF  [C0402]
C274  100NF  [C0402]
C275  1UF  [C0402]
C1212  22UF  [C0805_H61]
C1213  22UF  [C0805_H61]
C1215  22UF  [C0805_H61]
C1216  22UF  [C0805_H61]
C1245  1UF  [C0402]
C1246  1UF  [C0402]
C1247  1UF  [C0402]
C1248  1UF  [C0402]
R3541  100K  [R0402]
R3542  100K  [R0402]
R3543  100K  [R0402]
R3544  100K  [R0402]
R4000  22  [R0402]
R4001  22  [R0402]
R4002  22  [R0402]
R4003  22  [R0402]
R4396  0  [R0402]
R4397  0  [R0402]
R4398  0  [R0402]
R4399  0  [R0402]
U28  NCP45750IMN24TWG  [DFN12_TH_0-5_3X3XA]
U29  NCP45750IMN24TWG  [DFN12_TH_0-5_3X3XA]
U30  NCP45750IMN24TWG  [DFN12_TH_0-5_3X3XA]
U31  NCP45750IMN24TWG  [DFN12_TH_0-5_3X3XA]
sheet 048 LED
D1  LED BLUE  [LED_LTSTS270KSKT]
D5  LED BLUE  [LED_LTSTS270KSKT]
Q24  DMN2400UV-7  [SOT563-6XA]
R2875  2.7K  [R0603]
R3437  412  [R0402]
R4233  1K  [R0402]

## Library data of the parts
J6 = SCONN134_MDT670M01005: CONN SMD HOUSING 150P 2R FR(P0.5,H6.7); CLASS: IO; ESD_CDM: N/A; ESD_HBM: N/A; ESD_MM: N/A; MATERIAL: IO; MSD: NA; Manuf_PN: MDT670M01005; Manuf_name: AMPHENOL EAST ASIA LIMITED (Amphenol-TCS) (Shangh; Manuftr: APL; PIN_LENGTH_LONG_PIN: 20MILS; PIN_LENGTH_SHORT_PIN: 20MILS; Part_Type: *LF_Connector
C18 C21 C92 C140-C145 C258-C263 = CAP_NP: CAP CHIP 100NF 50V(+-10%,X7R,0402); CLASS: DISCRETE; MATERIAL: X7R; Manuf_PN: CC0402KRX7R9BB104; Manuf_name: YAGEO CORPORATION; Manufacturer: MUR; Manuftr: YGO; Part_Type: *LF_C0402; TOLERANCE: 10%; VOLTAGE: 50V
C164 C166 C168 C1134 C1137 C1140 C1143 C1146 C1149 = CAP_NP: CAP CHIP 1UF 25V(+-10%,X6S,0402); CLASS: DISCRETE; MATERIAL: X6S; Manuf_PN: GRM155C81E105K; Manuf_name: MURATA ERIE N.A. INC TAIWAN BRANCH Okayama Murata Mfg.Co..Ltd.Wakura Murata Mfg.; Manuftr: MUR; Part_Type: *LF_C0402; TOLERANCE: 10%; VOLTAGE: 25V
C146-C151 C165 C167 C169 C251 C264 C265 C268 C272 C278 = CAP_NP: CAP CHIP 10U 16V(+-20%,X6S,0603); CLASS: DISCRETE; MATERIAL: X6S; Manuf_PN: GRM188C81C106M; Manuf_name: MURATA ERIE N.A. INC TAIWAN BRANCH Okayama Murata Mfg.Co..Ltd. Wakura Murata Mfg; Manuftr: MUR; Part_Type: *LF_C0603; TOLERANCE: 20%; VOLTAGE: 16V
C70 C103 C121 C122 C765 C1097 C1135 C1136 C1138 C1139 C1141 C1142 C1144 C1145 C1147 C1148 = CAP_NP: CAP CHIP 100NF 50V(+-10%,X7R,0402); CLASS: DISCRETE; MATERIAL: X7R; Manuf_PN: CC0402KRX7R9BB104; Manuf_name: YAGEO CORPORATION; Manufacturer: AVX; Manuftr: YGO; Part_Type: *LF_C0402; TOLERANCE: 10%; VOLTAGE: 50V
C1098 = CAP_NP: CAP CHIP 100NF 50V(+-10%,X7R,0402); CLASS: DISCRETE; MATERIAL: X7R; Manuf_PN: CC0402KRX7R9BB104; Manuf_name: YAGEO CORPORATION; Manuftr: YGO; Part_Type: *LF_C0402; TOLERANCE: 10%; VOLTAGE: 50V
R2780 R2799 R2800 R2841 R3301 R3302 R3808 R3821-R3825 R3834-R3838 R3847-R3851 R3860-R3864 R3873-R3877 = R: RES CHIP 4.7K 1/16W +-5% (0402); CLASS: DISCRETE; MATERIAL: CHIP; Manuf_PN: RR0510S-472-JN; Manuf_name: CYNTEC CO.. LTD.; Manufacturer: CYN; Manuftr: CYN; Part_Type: *LF_Resistor; TOLERANCE: 5%; WATTAGE: 1/16W
R3666 R3667 R3804 R3805 R3809-R3818 R3826-R3831 R3839-R3844 R3852-R3857 R3865-R3870 = R: RES CHIP 22 1/16W +-1%(0402); BOM: AST2300; CLASS: DISCRETE; MATERIAL: CHIP; Manuf_PN: CR0222R0F002S; Manuf_name: RTECH TECHNOLOGY CO..LTD. (Compostar); Manufacturer: CYN; Manuftr: RHT; Part_Type: *LF_Resistor; TOLERANCE: 1%; WATTAGE: 1/16W
R3669 = R: RES CHIP  0.005  1W +-1%(1206); CLASS: DISCRETE; ESD_CDM: NA; ESD_HBM: NA; ESD_MM: NA; MATERIAL: CHIP; MSD: NA; Manuf_PN: RLM12FTCMR005; Manuf_name: TA-I TECHNOLOGY CO.,LTD.; Manuftr: TAI; PIN_LENGTH_LONG_PIN: 0 MILS; PIN_LENGTH_SHORT_PIN: 0 MILS; Part_Type: *LF_Resistor; TOLERANCE: 1%; WATTAGE: 1W
R3670 R3671 = R: RES CHIP 10 1/16W +-1%(0402); CLASS: DISCRETE; MATERIAL: CHIP; Manuf_PN: RM04FTN10R0; Manuf_name: TA-I TECHNOLOGY CO..LTD.; Manuftr: TAI; Part_Type: *LF_Resistor; TOLERANCE: 1%; WATTAGE: 1/16W
R3678 R3691 R3889 = R: RES CHIP 4.7K 1/16W +-5% (0402); CLASS: DISCRETE; MATERIAL: CHIP; Manuf_PN: RR0510S-472-JN; Manuf_name: CYNTEC CO.. LTD.; Manuftr: CYN; Part_Type: *LF_Resistor; TOLERANCE: 5%; WATTAGE: 1/16W
R3994-R4005 R4022 = R: RES CHIP 22 1/16W +-1%(0402); CLASS: DISCRETE; MATERIAL: CHIP; Manuf_PN: CR0222R0F002S; Manuf_name: RTECH TECHNOLOGY CO..LTD. (Compostar); Manuftr: RHT; Part_Type: *LF_Resistor; TOLERANCE: 1%; WATTAGE: 1/16W
R4142 R4143 R4145 = R: RES CHIP 4.7K(1/20W,+-5%,0201); CLASS: DISCRETE; MATERIAL: CHIP; Manuf_PN: RR0306S-472-JN; Manuf_name: CYNTEC CO., LTD.; Manuftr: CYN; Not_insert: NI; Part_Type: *LF_Resistor; TOLERANCE: 5%; WATTAGE: 1/20W
R4144 = R: RES CHIP 4.7K(1/20W,+-5%,0201); CLASS: DISCRETE; MATERIAL: CHIP; Manuf_PN: RR0306S-472-JN; Manuf_name: CYNTEC CO., LTD.; Manuftr: CYN; Part_Type: *LF_Resistor; TOLERANCE: 5%; WATTAGE: 1/20W
R4256 R4257 R4289 = R: RESISTOR CHIP 0 1/16W +-5%(0402); CLASS: DISCRETE; MATERIAL: CHIP; Manuf_PN: RR0510X-000-XN; Manuf_name: CYNTEC CO.. LTD.; Manuftr: CYN; Not_insert: NI; Part_Type: *LF_Resistor; TOLERANCE: 5%; WATTAGE: 1/16W
R4273 = R: RES CHIP 4.7K 1/16W +-5% (0402); CLASS: DISCRETE; MATERIAL: CHIP; Manuf_PN: RR0510S-472-JN; Manuf_name: CYNTEC CO.. LTD.; Manufacturer: CYN; Manuftr: CYN; Not_insert: NI; Part_Type: *LF_Resistor; TOLERANCE: 5%; WATTAGE: 1/16W
R4305 = R: RESISTOR CHIP 0 1/16W +-5%(0402); CLASS: DISCRETE; MATERIAL: CHIP; Manuf_PN: RR0510X-000-XN; Manuf_name: CYNTEC CO.. LTD.; Manuftr: CYN; Part_Type: *LF_Resistor; TOLERANCE: 5%; WATTAGE: 1/16W
TP5 TP6 TP37 TP38 TP55 = TP: TEST POINT (TP26D10) DIP(DRILL10MILS); ALT_SYMBOLS: TOP:TP26D10;BOTTOM:TP30D10; CLASS: IO; Cost: CPU; DIP_SMD: DIP; MATERIAL: MISC; Not_insert: NI; Part_Type: Misc; SUBSYS: CPU_CONN
U79 = INA231AIYFFR: IC OTHER (12P) INA231AIYFFR (DSBGA); CLASS: IC; ESD_CDM: 1000; ESD_HBM: 2500; ESD_MM: 150; MATERIAL: IC; MSD: Level-1; Manuf_name: TEXAS INSTRUMENTS SUPPLY CO.,; Manuftr: TIC; PIN_LENGTH_LONG_PIN: 0 MILS; PIN_LENGTH_SHORT_PIN: 0 MILS; Part_Type: *LF_Chipset
R67-R78 R3063-R3074 = R: RES CHIP 2.2K 1/16W +-5%(0402)EF; CLASS: DISCRETE; FPLIST: R0402,R0402-0201; MATERIAL: CHIP; Manuf_PN: RC0402JR-072K2P; Manuf_name: YAGEO CORPORATION; Manufacturer: CYN; Manuftr: YGO; Part_Type: *LF_Resistor; TOLERANCE: 5%; WATTAGE: 1/16W
R3806 R3807 R3819 R3820 R3832 R3833 R3845 R3846 R3858 R3859 R3871 R3872 = R: RES CHIP 220 1/16W +-5%(0402); CLASS: DISCRETE; MATERIAL: CHIP; Manuf_PN: RR0510S-221-JN; Manuf_name: CYNTEC CO.. LTD.; Manuftr: CYN; Part_Type: *LF_Resistor; TOLERANCE: 5%; WATTAGE: 1/16W
U88-U93 = PCA9846PW: IC OTHER(16P)PCA9846PW(TSSOP); CLASS: IC; MATERIAL: IC; Manuf_name: NXP semiconductors; Manuftr: NXP; Part_Type: *LF_Chipset
C1229 = CAP_NP: CAP CHIP 100PF 16V(+-10%,X7R,0201); CLASS: DISCRETE; MATERIAL: X7R; Manuf_PN: GRM033R71C101K; Manuf_name: MURATA ERIE N.A. INC TAIWAN BRANCH Okayama Murata Mfg.Co.,Ltd.Wakura Murata Mfg.; Manuftr: MUR; Part_Type: *LF_C0201; TOLERANCE: 10%; VOLTAGE: 16V
R2847 = R: RES CHIP 100K 1/16W +-1% (0402); CLASS: DISCRETE; MATERIAL: CHIP; Manuf_PN: RR0510S-104-FN; Manuf_name: CYNTEC CO.. LTD.; Manuftr: CYN; Part_Type: *LF_Resistor; TOLERANCE: 1%; WATTAGE: 1/16W
R2848 = R: RES CHIP 10K 1/16W +-1% (0402); CLASS: DISCRETE; MATERIAL: CHIP; Manuf_PN: RR0510S-103-FN; Manuf_name: CYNTEC CO.. LTD.; Manuftr: CYN; Not_insert: NI; Part_Type: *LF_Resistor; TOLERANCE: 1%; WATTAGE: 1/16W
R2864-R2869 R2949-R2954 = R: RES CHIP 49.9 1/16W +-1% (0402); CLASS: DISCRETE; MATERIAL: CHIP; Manuf_PN: RR0510S-49R9-FN; Manuf_name: CYNTEC CO.. LTD.; Manuftr: CYN; Part_Type: *LF_Resistor; TOLERANCE: 1%; WATTAGE: 1/16W
R4288 = R: RES CHIP 22 1/16W +-1%(0402); CLASS: DISCRETE; FPLIST: R0402,R0402-0201; MATERIAL: CHIP; Manuf_PN: CR0222R0F002S; Manuf_name: RTECH TECHNOLOGY CO..LTD. (Compostar); Manuftr: RHT; Part_Type: *LF_Resistor; TOLERANCE: 1%; WATTAGE: 1/16W
U25 U26 U50 = 74LVC08: IC(14P) SN74LVC08APWR(TSSOP)EP; CLASS: IC; MATERIAL: IC; Manuf_name: TEXAS INSTRUMENTS SUPPLY CO..; Manuftr: TIC; Part_Type: *LF_Chipset; Preference: TOSHIBA
C49 C125 C128 C131 C134 C137 C267 C270 C273 C275 C277 C280 = CAP_NP: CAP CHIP 1UF 25V(+-10%,X6S,0402); CLASS: DISCRETE; MATERIAL: X6S; Manuf_PN: GRM155C81E105K; Manuf_name: MURATA ERIE N.A. INC TAIWAN BRANCH Okayama Murata Mfg.Co..Ltd.Wakura Murata Mfg.; Manufacturer: MUR; Manuftr: MUR; Part_Type: *LF_C0402; TOLERANCE: 10%; VOLTAGE: 25V
C104 C123 C126 C129 C132 C135 C266 C269 C271 C274 C276 C279 = CAP_NP: CAP CHIP 100NF 50V(+-10%,X7R,0402); CLASS: DISCRETE; FPLIST: C0402,C0402-0201; MATERIAL: X7R; Manuf_PN: CC0402KRX7R9BB104; Manuf_name: YAGEO CORPORATION; Manuftr: YGO; Part_Type: *LF_C0402; TOLERANCE: 10%; VOLTAGE: 50V
C188-C193 C252-C257 C1206-C1217 = CAP_NP: CAP CHIP 22U 10V(+-20%,X6S,0805)MUR; CLASS: DISCRETE; MATERIAL: X6S; Manuf_PN: GRM21BC81A226M; Manuf_name: MURATA ERIE N.A. INC TAIWAN BRANCH Okayama Murata Mfg.Co.,Ltd.Wakura Murata Mfg.; Manuftr: MUR; Part_Type: *LF_C0805; TOLERANCE: 20%; VOLTAGE: 10V
C1237-C1248 = CAP_NP: CAP CHIP 1UF 25V(+-10%,X6S,0402); CLASS: DISCRETE; FPLIST: C0402,C0402-0201; MATERIAL: X6S; Manuf_PN: GRM155C81E105K; Manuf_name: MURATA ERIE N.A. INC TAIWAN BRANCH Okayama Murata Mfg.Co..Ltd.Wakura Murata Mfg.; Manufacturer: MUR; Manuftr: MUR; Part_Type: *LF_C0402; TOLERANCE: 10%; VOLTAGE: 25V
R3535-R3546 = R: RES CHIP 100K 1/16W +-1% (0402); CLASS: DISCRETE; FPLIST: R0402,R0402-0201; MATERIAL: CHIP; Manuf_PN: RR0510S-104-FN; Manuf_name: CYNTEC CO.. LTD.; Manuftr: CYN; Part_Type: *LF_Resistor; TOLERANCE: 1%; WATTAGE: 1/16W
R4388-R4399 = R: RES CHIP 0 1/16W +-5%(0402)EF; CLASS: DISCRETE; FPLIST: R0402,R0402-0201; MATERIAL: CHIP; Manuf_PN: WR04X000PTR; Manuf_name: WALSIN TECHNOLOGY CORPORATION; Manuftr: WTC; Part_Type: *LF_Resistor; TOLERANCE: 5%; WATTAGE: 1/16W
U19-U24 U28-U33 = NCP45750IMN24TWG: IC OTHER(12P)NCP45750IMN24TWG(DFN); CLASS: IC; ESD_CDM: 1000; ESD_HBM: 2000; ESD_MM: N/A; MATERIAL: IC; MSD: NA; Manuf_name: ON SEMICONDUCTOR; Manuftr: ONS; PIN_LENGTH_LONG_PIN: 0 MILS; PIN_LENGTH_SHORT_PIN: 0 MILS; Part_Type: *LF_Chipset
D1 D5 = LED_12: LED SMD (2P) BLUE (LTST-S270TBKT-5A)EP; CLASS: IC; EE_CHECK_LIST: LED_LTSTS270KSKT.xls; MATERIAL: IC; Manuf_PN: LTST-S270TBKT-5A; Manuf_name: TAIWAN LITEON ELECTRONIC CO.. LTD.; Manuftr: LIT; Part_Type: *LF_Semiconductor
Q24 = MOSFET_DUAL_6P: TRANS MOS DMN2400UV-7(20V,1.33A,0.53W); CLASS: IC; MATERIAL: IC; Manuf_name: DIODES TAIWAN CO.,LTD.(Kai Hong Shanghai); Manuftr: DDS; Part_Type: *LF_Semiconductor
R2875 = R: RES CHIP 2.7K 1/10W +-5%(0603); CLASS: DISCRETE; MATERIAL: CHIP; Manuf_PN: RTT03272JTP; Manuf_name: RALEC ELECTRONIC CO.; Manuftr: RLC; Part_Type: *LF_Resistor; TOLERANCE: 5%; WATTAGE: 1/10W
R3437 = R: RESISTOR CHIP 412 1/16W +-1%(0402); CLASS: DISCRETE; MATERIAL: CHIP; Manuf_PN: CR02412RF002S; Manuf_name: RTECH TECHNOLOGY CO..LTD.(Compostar); Manuftr: RHT; Part_Type: *LF_Resistor; TOLERANCE: 1%; WATTAGE: 1/16W
R4233 = R: RES CHIP 1K 1/16W +-1% (0402); CLASS: DISCRETE; MATERIAL: CHIP; Manuf_PN: RR0510S-102-FN; Manuf_name: CYNTEC CO.. LTD.; Manuftr: CYN; Part_Type: *LF_Resistor; TOLERANCE: 1%; WATTAGE: 1/16W

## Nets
GND: C18.2 C21.2 C49.2 C70.2 C92.2 C103.2 C104.2 C121.2 C122.2 C123.2 C125.2 C126.2 C128.2 C129.2 C131.2 C132.2 C134.2 C135.2 C137.2 C140.2 C141.2 C142.2 C143.2 C144.2 C145.2 C146.2 C147.2 C148.2 C149.2 C150.2 C151.2 C164.2 C165.2 C166.2 C167.2 C168.2 C169.2 C188.2 C189.2 C190.2 C191.2 C192.2 C193.2 C251.2 C252.2 C253.2 C254.2 C255.2 C256.2 C257.2 C258.2 C259.2 C260.2 C261.2 C262.2 C263.2 C264.2 C265.2 C266.2 C267.2 C268.2 C269.2 C270.2 C271.2 C272.2 C273.2 C274.2 C275.2 C276.2 C277.2 C278.2 C279.2 C280.2 C765.2 C1097.2 C1134.2 C1135.2 C1136.2 C1137.2 C1138.2 C1139.2 C1140.2 C1141.2 C1142.2 C1143.2 C1144.2 C1145.2 C1146.2 C1147.2 C1148.2 C1149.2 C1206.2 C1207.2 C1208.2 C1209.2 C1210.2 C1211.2 C1212.2 C1213.2 C1214.2 C1215.2 C1216.2 C1217.2 C1229.2 C1237.2 C1238.2 C1239.2 C1240.2 C1241.2 C1242.2 C1243.2 C1244.2 C1245.2 C1246.2 C1247.2 C1248.2 D1.2 J6.A1(GND3) J6.A3(GND4) J6.A9(GND5) J6.A15(GND6) J6.A21(GND7) J6.A27(GND8) J6.A32(GND1) J6.A33(GND9) J6.A38(GND2) J6.A39(GND10) J6.A45(GND11) J6.A51(GND12) J6.A57(GND13) J6.A71(GND14) J6.A75(GND15) J6.G1 J6.G2 Q24.1(S1) Q24.4(S2) Q24.5(G2) R2847.2 R3806.2 R3807.2 R3819.2 R3820.2 R3832.2 R3833.2 R3845.2 R3846.2 R3858.2 R3859.2 R3871.2 R3872.2 R4144.2 R4145.2 R4233.2 R4257.1 R4388.2 R4389.2 R4390.2 R4391.2 R4392.2 R4393.2 R4394.2 R4395.2 R4396.2 R4397.2 R4398.2 R4399.2 U19.6(VSS) U20.6(VSS) U21.6(VSS) U22.6(VSS) U23.6(VSS) U24.6(VSS) U25.7(GND) U26.7(GND) U28.6(VSS) U29.6(VSS) U30.6(VSS) U31.6(VSS) U32.6(VSS) U33.6(VSS) U50.7(GND) U79.C1(GND) U88.8(VSS) U89.8(VSS) U90.8(VSS) U91.8(VSS) U92.8(VSS) U93.8(VSS) ; also on sheet 12 13 17 18 19 20 21 22 23 24 25 26 27 28 29 30 31 32 33 34 43 44 45 46 47 48 49 50 52 53 54 55 56 57 58 61 62 63 64 65 66 67
P1V8: C70.1 C1136.1 C1139.1 C1142.1 C1145.1 C1148.1 R67.1 R68.1 R69.1 R70.1 R71.1 R72.1 R73.1 R74.1 R75.1 R76.1 R77.1 R78.1 R3063.1 R3064.1 R3065.1 R3066.1 R3067.1 R3068.1 R3069.1 R3070.1 R3071.1 R3072.1 R3073.1 R3074.1 R4256.1 U88.16(VDD2) U89.16(VDD2) U90.16(VDD2) U91.16(VDD2) U92.16(VDD2) U93.16(VDD2) ; also on sheet 17 18 19 22 23 24 25 26 27 28 29 30 31 32 33 34 44 49 50 53 58 62 65 67
P3V3_M2A: C49.1 U19.1(VOUT1) U19.2(VOUT2) U19.3(VOUT3) U19.4(VOUT4) U19.5(VOUT5) ; also on sheet 24
P3V3_M2A_EN: R2864.2 ; also on sheet 46 54
P3V3_M2A_EN_R: R2864.1 U25.3(Y)
P3V3_M2A_SR: C104.1 U19.7(SR)
P3V3_M2B: C125.1 U20.1(VOUT1) U20.2(VOUT2) U20.3(VOUT3) U20.4(VOUT4) U20.5(VOUT5) ; also on sheet 25
P3V3_M2B_EN: R2865.2 ; also on sheet 46 54
P3V3_M2B_EN_R: R2865.1 U25.6(Y)
P3V3_M2B_SR: C123.1 U20.7(SR)
P3V3_M2C: C128.1 U21.1(VOUT1) U21.2(VOUT2) U21.3(VOUT3) U21.4(VOUT4) U21.5(VOUT5) ; also on sheet 26
P3V3_M2C_EN: R2866.2 ; also on sheet 46 54
P3V3_M2C_EN_R: R2866.1 U25.8(Y)
P3V3_M2C_SR: C126.1 U21.7(SR)
P3V3_M2D: C131.1 U22.1(VOUT1) U22.2(VOUT2) U22.3(VOUT3) U22.4(VOUT4) U22.5(VOUT5) ; also on sheet 27
P3V3_M2D_EN: R2867.2 ; also on sheet 46 54
P3V3_M2D_EN_R: R2867.1 U25.11(Y)
P3V3_M2D_SR: C129.1 U22.7(SR)
P3V3_M2E: C134.1 U23.1(VOUT1) U23.2(VOUT2) U23.3(VOUT3) U23.4(VOUT4) U23.5(VOUT5) ; also on sheet 28
P3V3_M2E_EN: R2868.2 ; also on sheet 46 54
P3V3_M2E_EN_R: R2868.1 U26.3(Y)
P3V3_M2E_SR: C132.1 U23.7(SR)
P3V3_M2F: C137.1 U24.1(VOUT1) U24.2(VOUT2) U24.3(VOUT3) U24.4(VOUT4) U24.5(VOUT5) ; also on sheet 29
P3V3_M2F_EN: R2869.2 ; also on sheet 46 54
P3V3_M2F_EN_R: R2869.1 U26.6(Y)
P3V3_M2F_SR: C135.1 U24.7(SR)
P3V3_M2G: C280.1 U33.1(VOUT1) U33.2(VOUT2) U33.3(VOUT3) U33.4(VOUT4) U33.5(VOUT5) ; also on sheet 30
P3V3_M2G_EN: R2949.2 ; also on sheet 46 55
P3V3_M2G_EN_R: R2949.1 U26.8(Y)
P3V3_M2G_SR: C279.1 U33.7(SR)
P3V3_M2H: C277.1 U32.1(VOUT1) U32.2(VOUT2) U32.3(VOUT3) U32.4(VOUT4) U32.5(VOUT5) ; also on sheet 31
P3V3_M2H_EN: R2950.2 ; also on sheet 46 55
P3V3_M2H_EN_R: R2950.1 U26.11(Y)
P3V3_M2H_SR: C276.1 U32.7(SR)
P3V3_M2I: C275.1 U31.1(VOUT1) U31.2(VOUT2) U31.3(VOUT3) U31.4(VOUT4) U31.5(VOUT5) ; also on sheet 32
P3V3_M2I_EN: R2951.2 ; also on sheet 46 55
P3V3_M2I_EN_R: R2951.1 U50.3(Y)
P3V3_M2I_SR: C274.1 U31.7(SR)
P3V3_M2J: C273.1 U30.1(VOUT1) U30.2(VOUT2) U30.3(VOUT3) U30.4(VOUT4) U30.5(VOUT5) ; also on sheet 33
P3V3_M2J_EN: R2952.2 ; also on sheet 46 55
P3V3_M2J_EN_R: R2952.1 U50.6(Y)
P3V3_M2J_SR: C271.1 U30.7(SR)
P3V3_M2K: C270.1 U29.1(VOUT1) U29.2(VOUT2) U29.3(VOUT3) U29.4(VOUT4) U29.5(VOUT5) ; also on sheet 34
P3V3_M2K_EN: R2953.2 ; also on sheet 46 55
P3V3_M2K_EN_R: R2953.1 U50.8(Y)
P3V3_M2K_SR: C269.1 U29.7(SR)
P3V3_M2L: C267.1 R3669.2 R3670.1 U28.1(VOUT1) U28.2(VOUT2) U28.3(VOUT3) U28.4(VOUT4) U28.5(VOUT5) U79.D1(BUS)
P3V3_M2L_EN: R2954.2 ; also on sheet 46 55
P3V3_M2L_EN_R: R2954.1 U50.11(Y)
P3V3_M2L_L: C18.1 C21.1 C92.1 C164.1 C165.1 C166.1 C167.1 C168.1 C169.1 J6.A2(3.3V_1) J6.A4(3.3V_2) J6.A12(3.3V_3) J6.A14(3.3V_4) J6.A16(3.3V_5) J6.A18(3.3V_6) J6.A70(3.3V_7) J6.A72(3.3V_8) J6.A74(3.3V_9) R2780.2 R2841.1 R3669.1 R3671.1 R4142.1 R4143.1 R4273.2
P3V3_M2L_SR: C266.1 U28.7(SR)
P3V3_OR_M2A_EN: U19.11(EN) ; also on sheet 54
P3V3_OR_M2B_EN: U20.11(EN) ; also on sheet 54
P3V3_OR_M2C_EN: U21.11(EN) ; also on sheet 54
P3V3_OR_M2D_EN: U22.11(EN) ; also on sheet 54
P3V3_OR_M2E_EN: U23.11(EN) ; also on sheet 54
P3V3_OR_M2F_EN: U24.11(EN) ; also on sheet 54
P3V3_OR_M2G_EN: U33.11(EN) ; also on sheet 55
P3V3_OR_M2H_EN: U32.11(EN) ; also on sheet 55
P3V3_OR_M2I_EN: U31.11(EN) ; also on sheet 55
P3V3_OR_M2J_EN: U30.11(EN) ; also on sheet 55
P3V3_OR_M2K_EN: U29.11(EN) ; also on sheet 55
P3V3_OR_M2L_EN: U28.11(EN) ; also on sheet 55
P3V3_STBY: C103.1 C121.1 C122.1 C140.1 C141.1 C142.1 C143.1 C144.1 C145.1 C146.1 C147.1 C148.1 C149.1 C150.1 C151.1 C188.1 C189.1 C190.1 C191.1 C192.1 C193.1 C251.1 C252.1 C253.1 C254.1 C255.1 C256.1 C257.1 C258.1 C259.1 C260.1 C261.1 C262.1 C263.1 C264.1 C265.1 C268.1 C272.1 C278.1 C765.1 C1097.1 C1135.1 C1138.1 C1141.1 C1144.1 C1147.1 C1206.1 C1207.1 C1208.1 C1209.1 C1210.1 C1211.1 C1212.1 C1213.1 C1214.1 C1215.1 C1216.1 C1217.1 C1237.1 C1238.1 C1239.1 C1240.1 C1241.1 C1242.1 C1243.1 C1244.1 C1245.1 C1246.1 C1247.1 C1248.1 R2799.1 R2800.1 R2848.1 R3301.1 R3302.1 R3437.2 R3535.2 R3536.2 R3537.2 R3538.2 R3539.2 R3540.2 R3541.2 R3542.2 R3543.2 R3544.2 R3545.2 R3546.2 R3678.1 R3691.1 R3808.1 R3821.1 R3822.1 R3823.1 R3824.1 R3825.1 R3834.1 R3835.1 R3836.1 R3837.1 R3838.1 R3847.1 R3848.1 R3849.1 R3850.1 R3851.1 R3860.1 R3861.1 R3862.1 R3863.1 R3864.1 R3873.1 R3874.1 R3875.1 R3876.1 R3877.1 R3889.2 U19.10(VCC) U19.12(VIN2) U19.13(VIN1) U20.10(VCC) U20.12(VIN2) U20.13(VIN1) U21.10(VCC) U21.12(VIN2) U21.13(VIN1) U22.10(VCC) U22.12(VIN2) U22.13(VIN1) U23.10(VCC) U23.12(VIN2) U23.13(VIN1) U24.10(VCC) U24.12(VIN2) U24.13(VIN1) U25.14(VCC) U26.14(VCC) U28.10(VCC) U28.12(VIN2) U28.13(VIN1) U29.10(VCC) U29.12(VIN2) U29.13(VIN1) U30.10(VCC) U30.12(VIN2) U30.13(VIN1) U31.10(VCC) U31.12(VIN2) U31.13(VIN1) U32.10(VCC) U32.12(VIN2) U32.13(VIN1) U33.10(VCC) U33.12(VIN2) U33.13(VIN1) U50.14(VCC) U79.B1(VS) U88.1(VDD1) U89.1(VDD1) U90.1(VDD1) U91.1(VDD1) U92.1(VDD1) U93.1(VDD1) ; also on sheet 12 17 18 19 20 22 23 24 25 26 27 28 29 30 31 32 33 34 43 44 45 46 47 48 49 50 52 53 54 55 56 57 58 61 67
P12V_STBY: R2875.2 ; also on sheet 50 56 61
CLK_100M_DB1200_M2L_R_DN: J6.A53(REFCLKN) ; also on sheet 21
CLK_100M_DB1200_M2L_R_DP: J6.A55(REFCLKP) ; also on sheet 21
COM_CPLD_M2L_RX: J6.A46(UART_RX) ; also on sheet 52
COM_CPLD_M2L_TX: R4305.1 ; also on sheet 52
COM_CPLD_M2L_TX_R: J6.A48(UART_TX) R4305.2
FM_BIC_DEBUG_EN: Q24.2(G1) R4233.1 ; also on sheet 46
FM_M2A_OCP_ADJ: R4388.1 U19.9(OCP)
FM_M2B_OCP_ADJ: R4389.1 U20.9(OCP)
FM_M2C_OCP_ADJ: R4390.1 U21.9(OCP)
FM_M2D_OCP_ADJ: R4391.1 U22.9(OCP)
FM_M2E_OCP_ADJ: R4392.1 U23.9(OCP)
FM_M2F_OCP_ADJ: R4393.1 U24.9(OCP)
FM_M2G_OCP_ADJ: R4394.1 U33.9(OCP)
FM_M2H_OCP_ADJ: R4395.1 U32.9(OCP)
FM_M2I_OCP_ADJ: R4396.1 U31.9(OCP)
FM_M2J_OCP_ADJ: R4397.1 U30.9(OCP)
FM_M2K_OCP_ADJ: R4398.1 U29.9(OCP)
FM_M2L_OCP_ADJ: R4399.1 U28.9(OCP)
FM_POWER_EN: R4288.1 ; also on sheet 12 46
FM_POWER_EN_R1: C1229.1 R2847.1 R2848.2 R4288.2 R4289.2 U25.1(A) U25.4(A) U25.9(A) U25.12(A) U26.1(A) U26.4(A) U26.9(A) U26.12(A) U50.1(A) U50.4(A) U50.9(A) U50.12(A)
I2C_PESW_M2A_EN_LVC: U25.2(B) ; also on sheet 23
I2C_PESW_M2B_EN_LVC: U25.5(B) ; also on sheet 23
I2C_PESW_M2C_EN_LVC: U25.10(B) ; also on sheet 23
I2C_PESW_M2D_EN_LVC: U25.13(B) ; also on sheet 23
I2C_PESW_M2E_EN_LVC: U26.2(B) ; also on sheet 23
I2C_PESW_M2F_EN_LVC: U26.5(B) ; also on sheet 23
I2C_PESW_M2G_EN_LVC: U26.10(B) ; also on sheet 23
I2C_PESW_M2H_EN_LVC: U26.13(B) ; also on sheet 23
I2C_PESW_M2I_EN_LVC: U50.2(B) ; also on sheet 23
I2C_PESW_M2J_EN_LVC: U50.5(B) ; also on sheet 23
I2C_PESW_M2K_EN_LVC: U50.10(B) ; also on sheet 23
I2C_PESW_M2L_EN_LVC: U50.13(B) ; also on sheet 23
JTAG_CPLD_M2L_TCK: J6.A28(TCK) ; also on sheet 51
JTAG_CPLD_M2L_TDI: J6.A24(TDI) ; also on sheet 51
JTAG_CPLD_M2L_TDO: J6.A26(TDO) ; also on sheet 51
JTAG_CPLD_M2L_TMS: J6.A67(TMS) ; also on sheet 51
JTAG_CPLD_M2L_TRST: J6.A20(TRST) ; also on sheet 51
LED_FM_BIC_DEBUG_EN: D5.2 Q24.6(D1)
LED_FM_BIC_DEBUG_EN_R: D5.1 R3437.1
LED_P12V: D1.1 R2875.1
M2L_LED: J6.A10(LED_1#) R2841.2
M2L_VIO_CFG: J6.A73(VIO_CFG_GND) R4257.2
P3E_PESW_M2L_RX0_DN: J6.A41(PERN0) ; also on sheet 15
P3E_PESW_M2L_RX0_DP: J6.A43(PERP0) ; also on sheet 15
P3E_PESW_M2L_RX1_DN: J6.A29(PERN1) ; also on sheet 15
P3E_PESW_M2L_RX1_DP: J6.A31(PERP1) ; also on sheet 15
P3E_PESW_M2L_RX2_DN: J6.A17(PERN2) ; also on sheet 15
P3E_PESW_M2L_RX2_DP: J6.A19(PERP2) ; also on sheet 15
P3E_PESW_M2L_RX3_DN: J6.A5(PERN3) ; also on sheet 15
P3E_PESW_M2L_RX3_DP: J6.A7(PERP3) ; also on sheet 15
P3E_PESW_M2L_TX0_C_DN: J6.A47(PETN0) ; also on sheet 15
P3E_PESW_M2L_TX0_C_DP: J6.A49(PETP0) ; also on sheet 15
P3E_PESW_M2L_TX1_C_DN: J6.A35(PETN1) ; also on sheet 15
P3E_PESW_M2L_TX1_C_DP: J6.A37(PETP1) ; also on sheet 15
P3E_PESW_M2L_TX2_C_DN: J6.A23(PETN2) ; also on sheet 15
P3E_PESW_M2L_TX2_C_DP: J6.A25(PETP2) ; also on sheet 15
P3E_PESW_M2L_TX3_C_DN: J6.A11(PETN3) ; also on sheet 15
P3E_PESW_M2L_TX3_C_DP: J6.A13(PETP3) ; also on sheet 15
PD_I2C_MUX1_A0: R3806.1 U88.2(A0)
PD_I2C_MUX1_A1: R3807.1 U88.13(A1)
PD_I2C_MUX2_A0: R3819.1 U89.2(A0)
PD_I2C_MUX2_A1: R3820.1 U89.13(A1)
PD_I2C_MUX3_A0: R3832.1 U90.2(A0)
PD_I2C_MUX3_A1: R3833.1 U90.13(A1)
PD_I2C_MUX4_A0: R3845.1 U91.2(A0)
PD_I2C_MUX4_A1: R3846.1 U91.13(A1)
PD_I2C_MUX5_A0: R3858.1 U92.2(A0)
PD_I2C_MUX5_A1: R3859.1 U92.13(A1)
PD_I2C_MUX6_A0: R3871.1 U93.2(A0)
PD_I2C_MUX6_A1: R3872.1 U93.13(A1)
PD_M2L_PWRDIS: J6.A6(PWRDIS) R4143.2 R4144.1
PU_I2C_MUX1_SC2: R3301.2 U88.10(SC2)
PU_I2C_MUX1_SC3: R2799.2 U88.12(SC3)
PU_I2C_MUX1_SD2: R3302.2 U88.9(SD2)
PU_I2C_MUX1_SD3: R2800.2 U88.11(SD3)
PU_I2C_MUX2_SC2: R3825.2 U89.10(SC2)
PU_I2C_MUX2_SC3: R3822.2 U89.12(SC3)
PU_I2C_MUX2_SD2: R3824.2 U89.9(SD2)
PU_I2C_MUX2_SD3: R3823.2 U89.11(SD3)
PU_I2C_MUX3_SC2: R3838.2 U90.10(SC2)
PU_I2C_MUX3_SC3: R3835.2 U90.12(SC3)
PU_I2C_MUX3_SD2: R3837.2 U90.9(SD2)
PU_I2C_MUX3_SD3: R3836.2 U90.11(SD3)
PU_I2C_MUX4_SC2: R3851.2 U91.10(SC2)
PU_I2C_MUX4_SC3: R3848.2 U91.12(SC3)
PU_I2C_MUX4_SD2: R3850.2 U91.9(SD2)
PU_I2C_MUX4_SD3: R3849.2 U91.11(SD3)
PU_I2C_MUX5_SC2: R3864.2 U92.10(SC2)
PU_I2C_MUX5_SC3: R3861.2 U92.12(SC3)
PU_I2C_MUX5_SD2: R3863.2 U92.9(SD2)
PU_I2C_MUX5_SD3: R3862.2 U92.11(SD3)
PU_I2C_MUX6_SC2: R3877.2 U93.10(SC2)
PU_I2C_MUX6_SC3: R3874.2 U93.12(SC3)
PU_I2C_MUX6_SD2: R3876.2 U93.9(SD2)
PU_I2C_MUX6_SD3: R3875.2 U93.11(SD3)
PU_INA231_M2L_A0: R3678.2 U79.B3(A0)
PU_INA231_M2L_A1: R3691.2 U79.C3(A1)
PU_M2L_CLKREQ_N: J6.A52(CLKREQ#) R2780.1
PU_M2L_PLA_S3_N: J6.A30(PLA_S3#) R4273.1
PU_M2L_VIO_1V8: J6.A22(VIO_1V8) R4256.2
PWRGD_P1V8: R4289.1 ; also on sheet 19 23 58
PWRGD_P3V3_M2A: R3994.2 ; also on sheet 46
PWRGD_P3V3_M2A_R: R3535.1 R3994.1 U19.8(PG)
PWRGD_P3V3_M2B: R3995.2 ; also on sheet 46
PWRGD_P3V3_M2B_R: R3536.1 R3995.1 U20.8(PG)
PWRGD_P3V3_M2C: R3996.2 ; also on sheet 46
PWRGD_P3V3_M2C_R: R3537.1 R3996.1 U21.8(PG)
PWRGD_P3V3_M2D: R3997.2 ; also on sheet 46
PWRGD_P3V3_M2D_R: R3538.1 R3997.1 U22.8(PG)
PWRGD_P3V3_M2E: R3998.2 ; also on sheet 46
PWRGD_P3V3_M2E_R: R3539.1 R3998.1 U23.8(PG)
PWRGD_P3V3_M2F: R3999.2 ; also on sheet 46
PWRGD_P3V3_M2F_R: R3540.1 R3999.1 U24.8(PG)
PWRGD_P3V3_M2G: R4005.2 ; also on sheet 46
PWRGD_P3V3_M2G_R: R3546.1 R4005.1 U33.8(PG)
PWRGD_P3V3_M2H: R4004.2 ; also on sheet 46
PWRGD_P3V3_M2H_R: R3545.1 R4004.1 U32.8(PG)
PWRGD_P3V3_M2I: R4003.2 ; also on sheet 46
PWRGD_P3V3_M2I_R: R3544.1 R4003.1 U31.8(PG)
PWRGD_P3V3_M2J: R4002.2 ; also on sheet 46
PWRGD_P3V3_M2J_R: R3543.1 R4002.1 U30.8(PG)
PWRGD_P3V3_M2K: R4001.2 ; also on sheet 46
PWRGD_P3V3_M2K_R: R3542.1 R4001.1 U29.8(PG)
PWRGD_P3V3_M2L: R4000.2 ; also on sheet 46
PWRGD_P3V3_M2L_R: R3541.1 R4000.1 U28.8(PG)
RESERVED_M2L_PLN_N: J6.A8(PLN#) R4142.2 R4145.1
RST_I2C_MUX1_N: C1134.1 R3808.2 U88.3(RESET#) ; also on sheet 47
RST_I2C_MUX2_N: C1137.1 R3821.2 U89.3(RESET#) ; also on sheet 47
RST_I2C_MUX3_N: C1140.1 R3834.2 U90.3(RESET#) ; also on sheet 47
RST_I2C_MUX4_N: C1143.1 R3847.2 U91.3(RESET#) ; also on sheet 47
RST_I2C_MUX5_N: C1146.1 R3860.2 U92.3(RESET#) ; also on sheet 47
RST_I2C_MUX6_N: C1149.1 R3873.2 U93.3(RESET#) ; also on sheet 47
RST_PESW_M2L_LVC_N: J6.A50(PERST#) ; also on sheet 44
SMB_M2A_P1V8_CLK: R3809.2 ; also on sheet 24
SMB_M2A_P1V8_CLK_R2: R67.2 R3809.1 U88.5(SC0)
SMB_M2A_P1V8_DAT: R3810.2 ; also on sheet 24
SMB_M2A_P1V8_DAT_R2: R68.2 R3810.1 U88.4(SD0)
SMB_M2AB_3V3SB_CLK: R3804.1 ; also on sheet 46
SMB_M2AB_3V3SB_CLK_R1: R3804.2 U88.14(SCL)
SMB_M2AB_3V3SB_DAT: R3805.1 ; also on sheet 46
SMB_M2AB_3V3SB_DAT_R1: R3805.2 U88.15(SDA)
SMB_M2B_P1V8_CLK: R3811.2 ; also on sheet 25
SMB_M2B_P1V8_CLK_R2: R69.2 R3811.1 U88.7(SC1)
SMB_M2B_P1V8_DAT: R3812.2 ; also on sheet 25
SMB_M2B_P1V8_DAT_R2: R70.2 R3812.1 U88.6(SD1)
SMB_M2C_P1V8_CLK: R3813.2 ; also on sheet 26
SMB_M2C_P1V8_CLK_R2: R71.2 R3813.1 U89.5(SC0)
SMB_M2C_P1V8_DAT: R3814.2 ; also on sheet 26
SMB_M2C_P1V8_DAT_R2: R72.2 R3814.1 U89.4(SD0)
SMB_M2CD_3V3SB_CLK: R3817.1 ; also on sheet 46
SMB_M2CD_3V3SB_CLK_R1: R3817.2 U89.14(SCL)
SMB_M2CD_3V3SB_DAT: R3818.1 ; also on sheet 46
SMB_M2CD_3V3SB_DAT_R1: R3818.2 U89.15(SDA)
SMB_M2D_P1V8_CLK: R3815.2 ; also on sheet 27
SMB_M2D_P1V8_CLK_R2: R73.2 R3815.1 U89.7(SC1)
SMB_M2D_P1V8_DAT: R3816.2 ; also on sheet 27
SMB_M2D_P1V8_DAT_R2: R74.2 R3816.1 U89.6(SD1)
SMB_M2E_P1V8_CLK: R3826.2 ; also on sheet 28
SMB_M2E_P1V8_CLK_R2: R75.2 R3826.1 U90.5(SC0)
SMB_M2E_P1V8_DAT: R3827.2 ; also on sheet 28
SMB_M2E_P1V8_DAT_R2: R76.2 R3827.1 U90.4(SD0)
SMB_M2EF_3V3SB_CLK: R3830.1 ; also on sheet 46
SMB_M2EF_3V3SB_CLK_R1: R3830.2 U90.14(SCL)
SMB_M2EF_3V3SB_DAT: R3831.1 ; also on sheet 46
SMB_M2EF_3V3SB_DAT_R1: R3831.2 U90.15(SDA)
SMB_M2F_P1V8_CLK: R3828.2 ; also on sheet 29
SMB_M2F_P1V8_CLK_R2: R77.2 R3828.1 U90.7(SC1)
SMB_M2F_P1V8_DAT: R3829.2 ; also on sheet 29
SMB_M2F_P1V8_DAT_R2: R78.2 R3829.1 U90.6(SD1)
SMB_M2G_P1V8_CLK: R3839.2 ; also on sheet 30
SMB_M2G_P1V8_CLK_R2: R3063.2 R3839.1 U91.5(SC0)
SMB_M2G_P1V8_DAT: R3840.2 ; also on sheet 30
SMB_M2G_P1V8_DAT_R2: R3064.2 R3840.1 U91.4(SD0)
SMB_M2GH_3V3SB_CLK: R3843.1 ; also on sheet 46
SMB_M2GH_3V3SB_CLK_R1: R3843.2 U91.14(SCL)
SMB_M2GH_3V3SB_DAT: R3844.1 ; also on sheet 46
SMB_M2GH_3V3SB_DAT_R1: R3844.2 U91.15(SDA)
SMB_M2H_P1V8_CLK: R3841.2 ; also on sheet 31
SMB_M2H_P1V8_CLK_R2: R3065.2 R3841.1 U91.7(SC1)
SMB_M2H_P1V8_DAT: R3842.2 ; also on sheet 31
SMB_M2H_P1V8_DAT_R2: R3066.2 R3842.1 U91.6(SD1)
SMB_M2I_P1V8_CLK: R3852.2 ; also on sheet 32
SMB_M2I_P1V8_CLK_R2: R3067.2 R3852.1 U92.5(SC0)
SMB_M2I_P1V8_DAT: R3853.2 ; also on sheet 32
SMB_M2I_P1V8_DAT_R2: R3068.2 R3853.1 U92.4(SD0)
SMB_M2IJ_3V3SB_CLK: R3856.1 ; also on sheet 46
SMB_M2IJ_3V3SB_CLK_R1: R3856.2 U92.14(SCL)
SMB_M2IJ_3V3SB_DAT: R3857.1 ; also on sheet 46
SMB_M2IJ_3V3SB_DAT_R1: R3857.2 U92.15(SDA)
SMB_M2J_P1V8_CLK: R3854.2 ; also on sheet 33
SMB_M2J_P1V8_CLK_R2: R3069.2 R3854.1 U92.7(SC1)
SMB_M2J_P1V8_DAT: R3855.2 ; also on sheet 33
SMB_M2J_P1V8_DAT_R2: R3070.2 R3855.1 U92.6(SD1)
SMB_M2K_P1V8_CLK: R3865.2 ; also on sheet 34
SMB_M2K_P1V8_CLK_R2: R3071.2 R3865.1 U93.5(SC0)
SMB_M2K_P1V8_DAT: R3866.2 ; also on sheet 34
SMB_M2K_P1V8_DAT_R2: R3072.2 R3866.1 U93.4(SD0)
SMB_M2KL_3V3SB_CLK: R3869.1 ; also on sheet 46
SMB_M2KL_3V3SB_CLK_R1: R3869.2 U93.14(SCL)
SMB_M2KL_3V3SB_DAT: R3870.1 ; also on sheet 46
SMB_M2KL_3V3SB_DAT_R1: R3870.2 U93.15(SDA)
SMB_M2L_ALERT_N: J6.A44(ALERT#) ; also on sheet 49
SMB_M2L_INA231_ALRT_N: R4022.2 ; also on sheet 46
SMB_M2L_INA231_ALRT_N_R: R3889.1 R4022.1 U79.A3(ALERT)
SMB_M2L_INA231_CLK_R1: R3666.1 U79.A1(SCL)
SMB_M2L_INA231_DAT_R1: R3667.1 U79.A2(SDA)
SMB_M2L_P1V8_CLK: J6.A40(SMB_CLK) R3666.2 R3867.2
SMB_M2L_P1V8_CLK_R2: R3073.2 R3867.1 U93.7(SC1)
SMB_M2L_P1V8_DAT: J6.A42(SMB_DATA) R3667.2 R3868.2
SMB_M2L_P1V8_DAT_R2: R3074.2 R3868.1 U93.6(SD1)
TP_M2L_MFG_CLK: J6.A58(MFG_CLK) TP6.1
TP_M2L_MFG_DAT: J6.A56(MFG_DATA) TP5.1
TP_PEWAKE_M2L: J6.A54(PEWAKE#) TP55.1
TP_USB2_M2L_DN: J6.A36(USB_D-) TP37.1
TP_USB2_M2L_DP: J6.A34(USB_D+) TP38.1
VSENSE_P3V3_M2L_INA231_INN: C1098.2 R3671.2 U79.D2(IN-)
VSENSE_P3V3_M2L_INA231_INP: C1098.1 R3670.2 U79.D3(IN+)

Not connected (* = marked no-connect by the designer): J6 A68(NC1) A69(NC2); Q24 3(D2)*; U79 B2(NC)* C2(NC)*

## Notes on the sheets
sheet 35
- CAD Note:
  J6 is dual M.2 connector.
- SMBus (8-Bit) Address:0x8A
- M.2_L
sheet 36
- SMBus (8-Bit) Address:0xE2
- I2C MUX 1 (AB)
- SMBus (8-Bit) Address:0xE2
- I2C MUX 2 (CD)
- SMBus (8-Bit) Address:0xE2
- I2C MUX 3 (EF)
- I2C MUX 1-3
sheet 37
- SMBus (8-Bit) Address:0xE2
- I2C MUX 4 (GH)
- SMBus (8-Bit) Address:0xE2
- I2C MUX 5 (IJ)
- SMBus (8-Bit) Address:0xE2
- I2C MUX 6 (KL)
- I2C MUX 4-6
sheet 38
- CAD Note:
  C1229 place at near location(569.00 3158.00)
- P3V3 M.2 SWITCH 1
sheet 39
- P3V3 M.2 SWITCH 2
sheet 40
- P3V3 M.2 SWITCH 3
sheet 41
- P3V3 M.2 SWITCH 4
sheet 42
- P12V LED
- LAYOUT NOTE:
  Add SilkScreen "P12V_STBY" next to the LED
- BIC_DEBUG_EN LED
- All LEDs have to be placed along top edge of the card
- LED
